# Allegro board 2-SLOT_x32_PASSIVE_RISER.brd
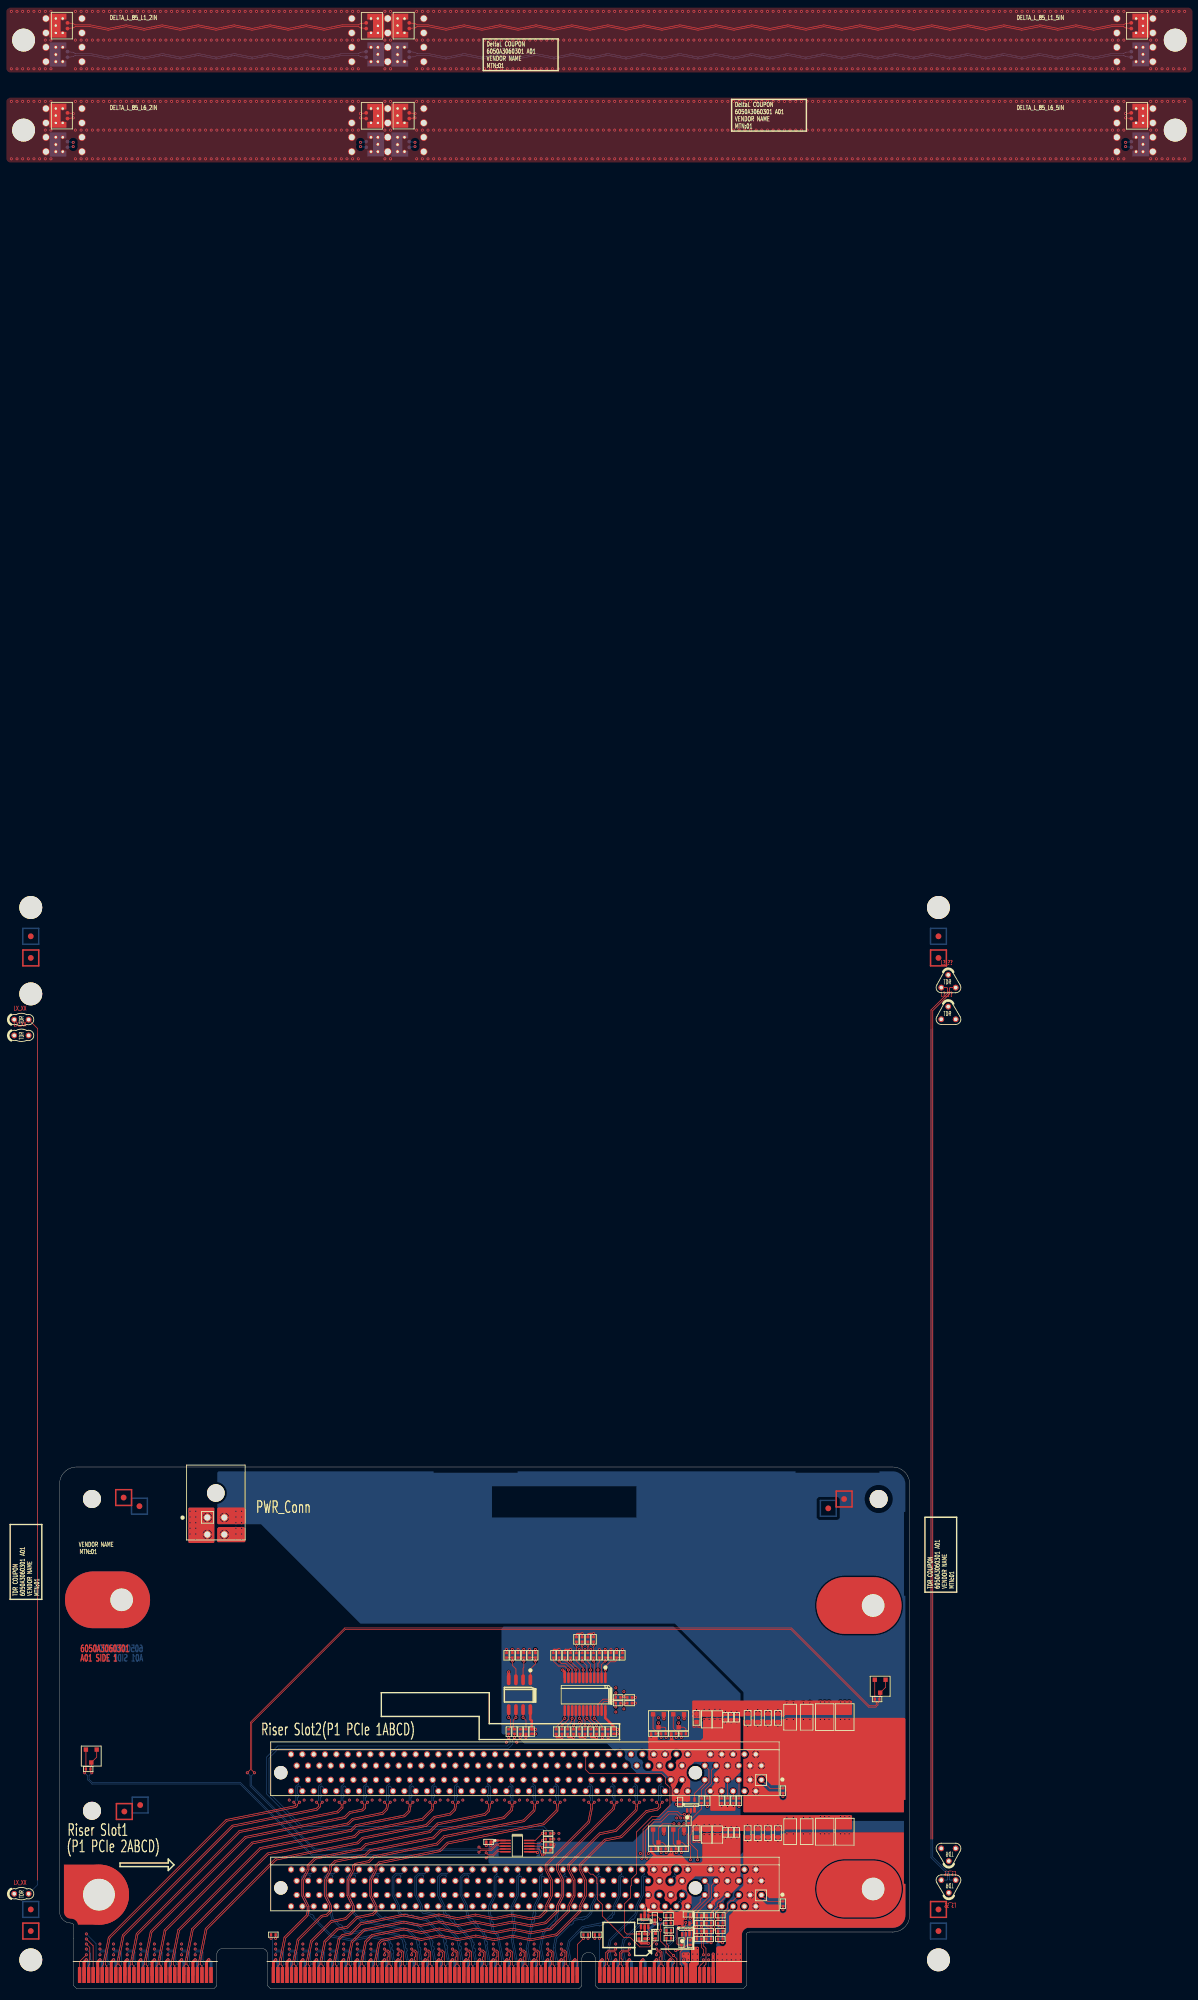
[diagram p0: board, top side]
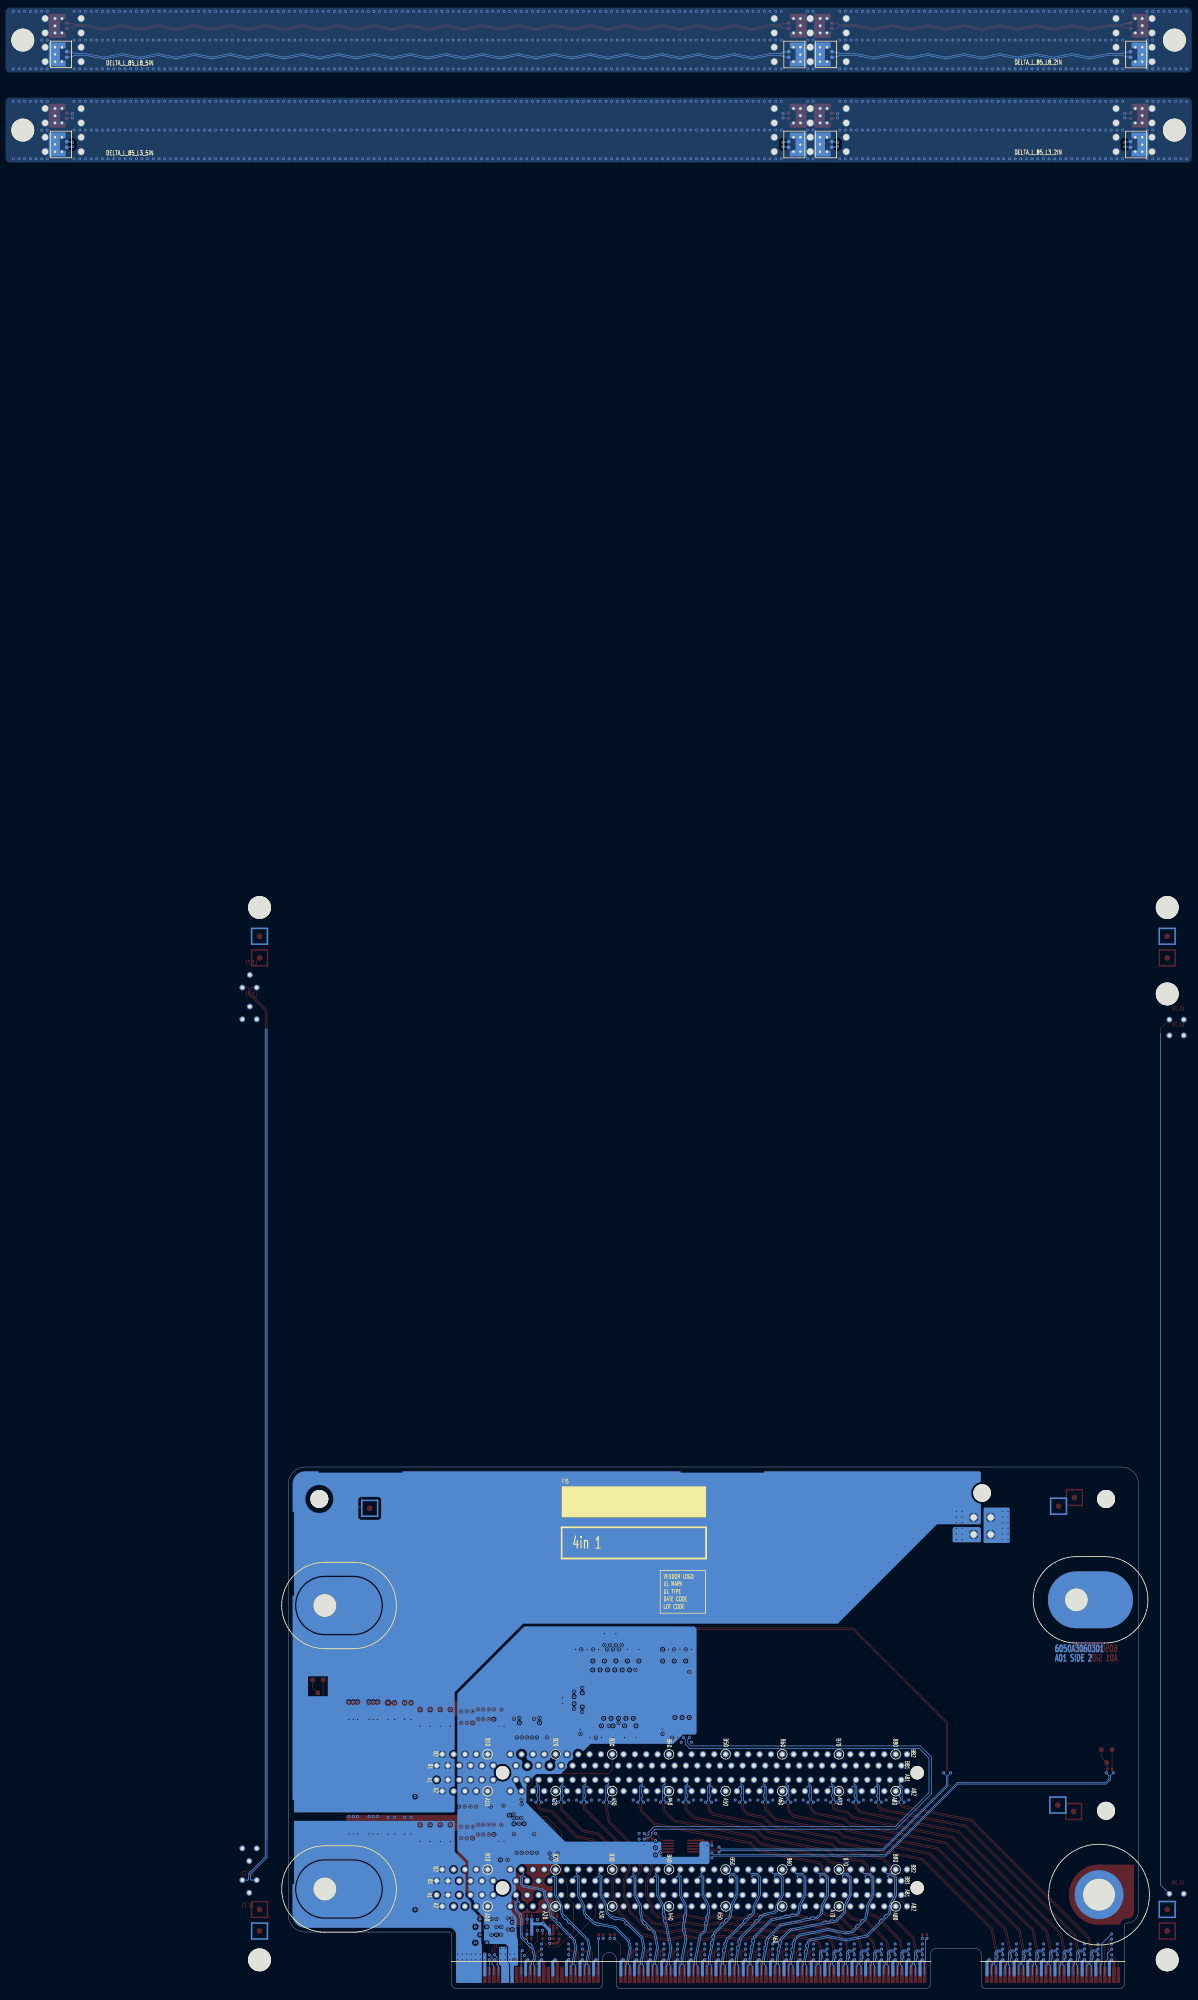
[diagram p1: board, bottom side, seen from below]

Outline 150 x 92 mm; copper layers: TOP, L2_GND, L3, L4_PWR, L5_PWR, L6, L7_GND, BOTTOM. Coordinates in mm from the lower left corner of the outline.
Outline path: 0,89 0,13.58 arc(0.59,12.16) 2,11.58 2,11.58 arc(2.36,11.43) 2.51,11.07 2.51,8.89 2.5,8.89 2.5,0.51 3.01,0 27.24,0 27.75,0.51 27.75,6.06 arc(28.05,6.78) 28.76,7.08 35.68,7.08 arc(36.4,6.78) 36.7,6.06 36.7,0.51 37.21,0 91.63,0 92.14,0.51 92.14,5.2 arc(93.34,6.4) 94.54,5.2 94.54,0.51 95.05,0 120.64,0 121.15,0.51 121.15,9.48 arc(121.3,9.84) 121.66,9.99 147,9.99 arc(149.12,10.86) 150,12.99 150,89 arc(149.12,91.12) 147,92 3,92 arc(0.88,91.12) 0,89

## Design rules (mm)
constraint set DEFAULT: min track width 0.102

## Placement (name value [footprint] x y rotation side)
C1  1uF  [A_MC-0603]  121.41 26.72 90 top
C2  1uF  [A_MC-0603]  123.19 26.72 90 top
C3  22uF  [A_MC-1206_A]  128.91 26.23 90 top
C4  22uF  [A_MC-1206_A]  131.83 26.23 90 top
C5  0.1UF  [A_MC-0402]  117.47 27.15 90 top
C6  0.1UF  [A_MC-0402]  118.49 27.15 90 top
C7  1uF  [A_MC-0402]  119.51 27.15 90 top
C8  4.7uF  [A_MC-0603]  124.97 26.72 90 top
C9  4.7uF  [A_MC-0603]  126.75 26.72 90 top
C10  4.7uF  [A_MC-0603]  112.39 26.72 90 top
C11  47uF  [A_MC-1210]  135 26.16 90 top
C12  10uF  [A_MC-0805]  116.08 26.3 90 top
C13  10uF  [A_MC-0805]  114.17 26.3 90 top
C14  0.1UF  [A_MC-0402]  103.24 9.64 270 top
C15  0.1UF  [A_MC-0402]  83.31 45.75 270 top
C16  0.1UF  [A_MC-0402]  97.79 45.75 270 top
C17  0.1UF  [A_MC-0402]  76.1 25.88 180 top
C18  22uF  [A_MC-1206_A]  128.91 46.42 90 top
C19  22uF  [A_MC-1206_A]  131.83 46.42 90 top
C20  47uF  [A_MC-1210]  135 46.35 90 top
C21  1uF  [A_MC-0603]  121.41 47.04 90 top
C22  1uF  [A_MC-0603]  126.75 47.04 90 top
C23  10uF  [A_MC-0805]  114.17 46.62 90 top
C24  10uF  [A_MC-0805]  116.08 46.62 90 top
C25  0.1UF  [A_MC-0402]  119.51 47.47 90 top
C26  0.1UF  [A_MC-0402]  117.47 47.47 90 top
C27  1uF  [A_MC-0402]  118.49 47.47 90 top
C28  4.7uF  [A_MC-0603]  124.97 47.04 90 top
C29  4.7uF  [A_MC-0603]  123.19 47.04 90 top
C30  100PF  [A_MC-0402]  144.65 51.05 180 top
C31  4.7uF  [A_MC-0603]  112.39 47.04 90 top
C32  100PF  [A_MC-0402]  4.65 38.73 0 top
C33  0.1UF  [A_MC-0402]  109.5 33.33 270 top
C34  0.1UF  [A_MC-0402]  110.46 13.08 0 top
C35  47uF  [A_MC-1210]  138.56 26.16 90 top
C36  47uF  [A_MC-1210]  138.56 46.35 90 top
J1  -  [A_FG-CN200-0P8MM_FULL_B]  120.13 2.4 180 top
J2  -  [FG-CN60-0P8MM_FULL_D]  26.72 2.4 180 top
J3  -  [A_CN164-2MM_FL]  123.84 16.52 180 top
J4  -  [A_CN164-2MM_FL]  123.84 36.84 180 top
J5  -  [A_SI_DELTAL_COUPON]  0.1 346.2 270 top
J6  -  [A_SI_DELTAL_COUPON]  55.41 346.2 90 top
J7  -  [A_SI_DELTAL_COUPON]  0.1 325.26 90 bottom
J8  -  [A_SI_DELTAL_COUPON]  55.41 325.25 270 bottom
J9  -  [A_SI_DELTAL_COUPON]  60.4 346.2 270 top
J10  -  [A_SI_DELTAL_COUPON]  190.4 346.2 90 top
J11  -  [A_SI_DELTAL_COUPON]  190.4 325.25 270 bottom
J12  -  [A_SI_DELTAL_COUPON]  60.4 325.26 90 bottom
J13  -  [A_CN4-3X3MM_ML_R_PIP]  26.07 83.1 180 top
J14  -  [A_SI_DELTAL_COUPON]  55.41 341.13 270 bottom
J15  -  [A_SI_DELTAL_COUPON]  55.41 330.33 90 top
J16  -  [A_SI_DELTAL_COUPON]  0.1 330.32 270 top
J17  -  [A_SI_DELTAL_COUPON]  0.1 341.13 90 bottom
J18  -  [A_SI_DELTAL_COUPON]  60.4 341.13 90 bottom
J19  -  [A_SI_DELTAL_COUPON]  190.4 330.33 90 top
J20  -  [A_SI_DELTAL_COUPON]  60.4 330.32 270 top
J22  -  [A_SI_DELTAL_COUPON]  190.4 341.13 270 bottom
MH1  -  [PAD_TP_D220_P339_K700_001]  6.95 16.58 270 bottom
MH2  -  [157X256_197_GRD_PTH]  10.95 68.58 180 bottom
MH3  -  [157X256_197_GRD_PTH]  143.55 17.58 180 bottom
MH4  -  [157X256_197_GRD_PTH]  143.55 67.58 180 bottom
NOREF  -  []  152 25.89 90 top
NOREF#2  -  []  12.74 101.75 0 top
NOREF#3  -  []  152 76.69 90 top
NOREF#4  -  [unnamed#2]  14.22 32.38 0 top
NOREF#5  -  [unnamed#2]  144.53 86.36 0 top
NOREF#6  -  []  73.41 91.59 0 top
NOREF#7  -  [unnamed#2]  196.85 327.79 270 top
NOREF#8  -  [unnamed#2]  -6.35 327.79 270 top
NOREF#9  -  []  -2.01 119.07 270 top
NOREF#10  -  []  12.74 91.59 0 top
NOREF#11  -  []  137.26 104.17 180 top
NOREF#12  -  [unnamed#2]  11.43 31.24 0 top
NOREF#13  -  [unnamed#2]  14.1 85.09 0 top
NOREF#14  -  [unnamed#2]  155.08 181.79 0 top
NOREF#15  -  []  137.26 91.59 0 top
NOREF#16  -  []  -2.01 76.69 270 top
NOREF#17  -  [unnamed#2]  11.3 86.61 0 top
NOREF#18  -  [unnamed#2]  -5.08 5.08 0 top
NOREF#19  -  [unnamed#2]  -5.08 185.6 0 top
NOREF#20  -  [unnamed#2]  155.08 185.6 0 top
NOREF#21  -  [unnamed#2]  -5.08 181.79 0 top
NOREF#22  -  [unnamed#2]  135.64 84.71 0 top
NOREF#23  -  [unnamed#2]  155.08 5.08 0 top
NOREF#24  -  [unnamed#2]  138.43 86.36 0 top
NOREF#25  -  [unnamed#2]  -6.35 343.67 270 top
NOREF#26  -  [unnamed#2]  155.08 10.16 180 top
NOREF#27  -  [unnamed#2]  196.85 343.67 270 top
NOREF#28  -  [unnamed#2]  5.71 31.37 0 top
NOREF#29  -  []  73.41 101.75 0 top
NOREF#30  -  [unnamed#2]  -5.08 190.68 0 top
NOREF#31  -  []  -2.01 25.89 270 top
NOREF#32  -  [unnamed#2]  -5.08 13.97 0 top
NOREF#33  -  [unnamed#2]  5.71 86.36 0 top
NOREF#34  -  [unnamed#2]  155.08 190.68 0 top
NOREF#35  -  [unnamed#2]  -5.08 10.16 0 top
NOREF#36  -  [unnamed#2]  -5.08 175.44 0 top
NOREF#37  -  [unnamed#2]  155.08 13.97 180 top
NOREF#38  -  []  -269.49 -130.56 0 top
NOREF#39  -  []  152 169.87 90 top
NOREF#40  -  []  152 119.07 90 top
NOREF#41  -  []  101.78 83.1 180 bottom
NOREF#42  -  []  101.78 75.86 180 bottom
NOREF#43  -  []  84.39 66.23 180 bottom
Q1  -  [A_SOT23FT]  106.63 48.39 180 top
Q2  -  [A_SOT23FT]  110.19 48.39 180 top
Q3  -  [A_SOT23FT]  110.19 28.07 180 top
Q4  -  [A_SOT23FT]  106.63 28.07 180 top
Q5  -  [A_SOT23FT]  145.75 54.48 180 top
Q6  -  [A_SOT23FT]  6.55 42.16 180 top
R1  0  [A_CR-0402]  111.25 7.72 90 top
R2  10K  [A_CR-0402]  96.77 45.75 270 top
R3  1K  [A_CR-0402]  95.76 44.93 90 top
R4  10K  [A_CR-0402]  78.87 58.39 90 top
R5  1K  [A_CR-0402]  79.88 59.21 270 top
R6  10K  [A_CR-0402]  97.28 58.39 90 top
R7  1K  [A_CR-0402]  96.27 59.21 270 top
R8  100  [A_CR-0402]  112.45 8.76 0 top
R9  10K  [A_CR-0402]  80.9 58.39 90 top
R10  1K  [A_CR-0402]  81.92 59.21 270 top
R11  10K  [A_CR-0402]  99.31 58.39 90 top
R12  1K  [A_CR-0402]  98.3 59.21 270 top
R13  10K  [A_CR-0402]  82.93 58.39 90 top
R14  100  [A_CR-0402]  112.45 10.16 0 top
R15  1K  [A_CR-0402]  83.95 59.21 270 top
R16  100  [A_CR-0402]  94.44 9.53 0 top
R17  10K  [A_CR-0402]  81.28 45.75 270 top
R18  100  [A_CR-0402]  93.24 9.53 180 top
R19  0  [A_CR-0402]  98.15 50.36 0 top
R20  0  [A_CR-0402]  107.09 8.89 0 top
R21  0  [A_CR-0402]  107.04 11.56 0 top
R22  4.7K  [A_CR-0402]  100.18 50.36 0 top
R23  4.7K  [A_CR-0402]  100.18 51.37 0 top
R24  4.7K  [A_CR-0402]  107.9 10.29 180 top
R25  4.7K  [A_CR-0402]  107.85 12.95 180 top
R26  0  [A_CR-0402]  109.73 7.72 90 top
R27  1K  [A_CR-0402]  82.3 44.93 90 top
R29  100  [A_CR-0402]  38.13 9.53 180 top
R30  0  [A_CR-0402]  80.26 45.75 270 top
R31  0  [A_CR-0402]  79.25 45.75 270 top
R32  0  [A_CR-0402]  94.23 58.39 90 top
R33  0  [A_CR-0402]  93.22 58.39 90 top
R34  0  [A_CR-0402]  92.2 58.39 90 top
R35  0  [A_CR-0402]  91.19 58.39 90 top
R36  0  [A_CR-0402]  85.79 27.39 0 top
R37  0  [A_CR-0402]  85.79 26.37 0 top
R38  100  [A_CR-0402]  127.64 34.52 90 top
R39  10K  [A_CR-0402]  117.86 33.55 270 top
R40  10K  [A_CR-0402]  118.87 33.55 270 top
R41  10K  [A_CR-0402]  114.3 32.74 90 top
R42  10K  [A_CR-0402]  116.84 33.55 270 top
R43  10K  [A_CR-0402]  119.89 32.74 90 top
R44  100  [A_CR-0402]  127.64 14.58 90 top
R45  10K  [A_CR-0402]  114.96 12.95 180 top
R46  10K  [A_CR-0402]  116.99 10.16 180 top
R47  10K  [A_CR-0402]  113.26 12.95 180 top
R48  10K  [A_CR-0402]  114.96 10.16 180 top
R49  10K  [A_CR-0402]  116.18 12.95 0 top
R50  0  [A_CR-0402]  114.96 11.56 180 top
R51  0  [A_CR-0402]  116.99 8.76 180 top
R52  0  [A_CR-0402]  111 29.18 90 top
R54  0  [A_CR-0402]  113.28 32.74 90 top
R55  0  [A_CR-0402]  114.96 8.76 180 top
R56  0  [A_CR-0402]  116.99 11.56 180 top
R57  0  [A_CR-0402]  98.15 51.37 0 top
R58  0  [A_CR-0402]  112.45 11.56 0 top
R59  0  [A_CR-0402]  106.96 44.96 180 top
R60  0  [A_CR-0402]  110.52 44.96 180 top
R61  0  [A_CR-0402]  110.52 24.64 180 top
R62  0  [A_CR-0402]  106.96 24.64 180 top
R63  4.7K  [A_CR-0402]  90.17 58.39 90 top
R64  4.7K  [A_CR-0402]  89.15 58.39 90 top
R65  4.7K  [A_CR-0402]  88.14 58.39 90 top
R66  4.7K  [A_CR-0402]  87.12 58.39 90 top
R67  4.7K  [A_CR-0402]  87.63 45.75 270 top
R68  4.7K  [A_CR-0402]  88.65 45.75 270 top
R69  4.7K  [A_CR-0402]  89.66 45.75 270 top
R70  4.7K  [A_CR-0402]  90.68 45.75 270 top
R71  4.7K  [A_CR-0402]  93.73 45.75 270 top
R72  4.7K  [A_CR-0402]  94.74 45.75 270 top
R74  100K  [A_CR-0402]  105.03 12.17 90 top
R98  4.7K  [A_CR-0402]  102.23 9.64 270 top
R99  4.7K  [A_CR-0402]  105.16 8.86 90 top
R100  4.7K  [A_CR-0402]  108.74 24.64 180 top
R101  4.7K  [A_CR-0402]  105.18 24.64 180 top
R102  4.7K  [A_CR-0402]  105.18 44.96 180 top
R103  4.7K  [A_CR-0402]  108.74 44.96 180 top
R104  4.7K  [A_CR-0402]  85.79 24.38 0 top
R105  4.7K  [A_CR-0402]  85.83 25.4 0 top
R106  4.7K  [A_CR-0402]  91.19 61.19 90 top
R107  4.7K  [A_CR-0402]  92.2 61.19 90 top
R108  4.7K  [A_CR-0402]  93.22 61.19 90 top
R109  4.7K  [A_CR-0402]  94.23 61.19 90 top
R110  4.7K  [A_CR-0402]  91.69 45.75 270 top
R111  4.7K  [A_CR-0402]  92.71 45.75 270 top
R112  4.7K  [A_CR-0402]  95.25 58.39 90 top
TDR1  -  [A_COUPON1X3]  155.57 176.56 0 top
TDR2  -  [A_COUPON1X3]  155.57 170.97 0 top
TDR3  -  [A_COUPON1X3]  158.12 24.74 180 top
TDR4  -  [A_COUPON1X3]  158.12 19.15 180 top
TDR5  -  [A_COUPON1X2]  -8 170.91 0 top
TDR6  -  [A_COUPON1X2]  -8 168.12 0 top
TDR8  -  [A_COUPON1X2]  -8 16.73 0 top
U1  -  [A_SC70-0P65MM-6P]  103.89 12.83 180 top
U2  -  [A_SSOP24-25P6X228]  96.29 54.84 180 top
U4  -  [A_MSOP10-19P7X165]  78.68 26.14 270 top
U5  -  [A_SOIC8-50X208]  83.06 54.48 180 top
U6  -  [A_SC70-0P65MMX1P9MM]  109.84 9.59 0 top
U7  -  [A_SC70-0P65MMX1P9MM]  110.73 31.43 0 top

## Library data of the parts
C1 C2 C21 C22 = A_CAP: alternate symbols: (); part number: A_CAP_0603-1UF,16V,+/-10%,X7R,6010B0106601; signal model: C2_6010B0106601_1U; tolerance: +/-10%
C3 C4 C18 C19 = A_CAP: alternate symbols: (); part number: A_CAP_1206-22UF,16V,+/-10%,X6S,6010B0309401; signal model: C2_6010B0309401_22U; tolerance: +/-10%
C5 C6 C14-C17 C25 C26 C33 C34 = A_CAP: alternate symbols: (A_MC-0402_CUTPAD,A_MC-0402_CUTPAD_0P8MM); part number: A_CAP_0402-0.1UF,16V,+/-10%,X7R,6010A0036403; signal model: C2_6010A0036403_0_1U; tolerance: +/-10%
C7 C27 = A_CAP: alternate symbols: (A_MC-0402_CUTPAD,A_MC-0402_CUTPAD_0P8MM); part number: A_CAP_0402-1UF,6.3V,+/-10%,X7R,6010B0435701; signal model: C2_6010B0435701_1U; tolerance: +/-10%
C8-C10 C28 C29 C31 = A_CAP: alternate symbols: (); part number: A_CAP_0603-4.7UF,16V,+/-10%,X6S,6010B0347201; signal model: C2_6010B0347201_4_7U; tolerance: +/-10%
C11 C20 C35 C36 = A_CAP: alternate symbols: (); part number: A_CAP_1210-47UF,16V,+/-20%,X6S,6010B0367101; signal model: C2_6010B0367101_47U; tolerance: +/-20%
C12 C13 C23 C24 = A_CAP: alternate symbols: (); part number: A_CAP_0805-10UF,16V,+/-10%,X7R,6010B0152001; signal model: C2_6010B0152001_10U; tolerance: +/-10%
C30 C32 = A_CAP: alternate symbols: (A_MC-0402_CUTPAD,A_MC-0402_CUTPAD_0P8MM); part number: A_CAP_0402-100PF,50V,+/-5%,NP0,6010A003610J; signal model: C2_6010A003610J_100P; tolerance: +/-5%
J1 = A_HSEC8_2X100_FG: part number: A_HSEC8_2X100_FG_HSEC8_FG-FG-CN200-0P8MM_FULL_B
J2 = A_2X30_2MP_B_FG: alternate symbols: (); part number: A_2X30_2MP_B_FG_FG-FG-CN60-0P8MM_FULL_D
J3 J4 = A_PCIE16X: alternate symbols: (); part number: A_PCIE16X_PCIE16X-6012B0820801
J5-J12 J14-J20 J22 = A_SI_DELTAL_COUPON: part number: A_SI_DELTAL_COUPON_COUPON-SI_DELTAL_COUPON
J13 = A_2X2: alternate symbols: (); part number: A_2X2_CN4-6012B0884101
MH1 = A_TOOL1X1: part number: A_TOOL1X1_1X1-PAD_TP_D220_P339_K700_001
MH2-MH4 = A_TOOL1X1: part number: A_TOOL1X1_1X1-157X256_197_GRD_PTH
Q1-Q4 = A_NMFET_A: alternate symbols: (); part number: A_NMFET_A_SOT23-NX7002BKR,-,60V,+/-20V,6015B0042607
Q5 Q6 = A_NPN: alternate symbols: (); part number: A_NPN_SM-PMBT3904,40V,-,-,6015B0007101
R1 R19-R21 R26 R30-R37 R50-R52 R54-R62 = A_RES_SMT: alternate symbols: (A_CR-0402_CUTPAD_0P8MM,A_CR-0402_CUTPAD); part number: A_RES_SMT_0402-0,5%,1A,6013B0051101; signal model: R2_6013B0051101_0; tolerance: 5%
R2 R4 R6 R9 R11 R13 R17 R39-R43 R45-R49 = A_RES_SMT: alternate symbols: (A_CR-0402_CUTPAD_0P8MM,A_CR-0402_CUTPAD); part number: A_RES_SMT_0402-10K,1%,1/16,6013A008830M; signal model: R2_6013A008830M_10K; tolerance: 1%
R3 R5 R7 R10 R12 R15 R27 = A_RES_SMT: alternate symbols: (A_CR-0402_CUTPAD_0P8MM,A_CR-0402_CUTPAD); part number: A_RES_SMT_0402-1K,1%,1/16W,6013A0088009; signal model: R2_6013A0088009_1K; tolerance: 1%
R8 R14 R16 R18 R29 R38 R44 = A_RES_SMT: alternate symbols: (A_CR-0402_CUTPAD_0P8MM,A_CR-0402_CUTPAD); part number: A_RES_SMT_0402-100,1%,1/16W,6013A008760S; signal model: R2_6013A008760S_100; tolerance: 1%
R22-R25 R63-R72 R98-R112 = A_RES_SMT: alternate symbols: (A_CR-0402_CUTPAD_0P8MM,A_CR-0402_CUTPAD); part number: A_RES_SMT_0402-4.7K,1%,1/16W,6013B0080101; signal model: R2_6013B0080101_4_7K; tolerance: 1%
R74 = A_RES_SMT: alternate symbols: (A_CR-0402_CUTPAD_0P8MM,A_CR-0402_CUTPAD); part number: A_RES_SMT_0402-100K,1%,1/16,6013A0088705; signal model: R2_6013A0088705_100K; tolerance: 1%
TDR1-TDR4 = A_COUPON1X3: part number: A_COUPON1X3_1X3-COUPON1X3-00
TDR5 TDR6 TDR8 = A_COUPON1X2: part number: A_COUPON1X2_1X2-COUPON1X2-00
U1 = A_NC7WV07: alternate symbols: (); part number: A_NC7WV07_SC70-NC7WV07P6X,6019B0664001
U2 = A_PCA9548A: alternate symbols: (); part number: A_PCA9548A_TSSOP-PCA9548APW,118,6019B0191601
U4 = A_EMC1413: alternate symbols: (); part number: A_EMC1413_MSOP-EMC1413-A-AIZL-TR,6019B1799701
U5 = A_24CX: alternate symbols: (); part number: A_24CX_SOIC8-24C64CN-SH-T,6019B0493601
U6 U7 = A_TSG17: alternate symbols: (); part number: A_TSG17_SC70-SN74LVC1G17DCKR,6019B0306901

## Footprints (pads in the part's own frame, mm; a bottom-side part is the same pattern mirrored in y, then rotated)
157X256_197_GRD_PTH
  oval 15.011x10.008 hole 3.988: 1(0,0)
A_CN4-3X3MM_ML_R_PIP
  round 3.099 hole 3.099 unplated: (-1.5,-4.32)
  round 1.448 hole 1.067: 1(0,0) 2(-3,0) 3(0,3) 4(-3,3)
A_CN164-2MM_FL
  round 2.362 hole 2.362 unplated: (11.65,-1.25) (84.8,-1.25)
  round 1.092 hole 0.711: A1(0,0) A2(0.999,2) A3(2,0) A4(3,2) A5(4,0) A6(5,2) A7(5.999,0) A8(7,2) A9(8,0) A10(9,2) A11(10,0) A12(13,2) A13(14,0) A14(15,2) A15(15.999,0) A16(17,2) A17(18,0) A18(19,2) A19(20,0) A20(20.999,2) A21(22,0) A22(23,2) A23(24,0) A24(25,2) A25(25.999,0) A26(27,2) A27(28,0) A28(29,2) A29(30,0) A30(30.999,2) A31(32,0) A32(33,2) A33(34,0) A34(35,2) A35(35.999,0) A36(37,2) A37(38,0) A38(39,2) A39(40,0) A40(40.999,2) A41(42,0) A42(43,2) A43(44,0) A44(45,2) A45(45.999,0) A46(47,2) A47(48,0) A48(49,2) A49(50,0) A50(50.999,2) A51(52,0) A52(53,2) A53(54,0) A54(55,2) A55(55.999,0) A56(57,2) A57(58,0) A58(59,2) A59(60,0) A60(60.999,2) A61(62,0) A62(63,2) A63(64,0) A64(65,2) A65(66.001,0) A66(67,2) A67(68,0) A68(69,2) A69(70,0) A70(71.001,2) A71(72,0) A72(73,2) A73(74,0) A74(75,2) A75(76.001,0) A76(77,2) A77(78,0) A78(79,2) A79(80,0) A80(81.001,2) A81(82,0) A82(83,2) B1(0,-2.501) B2(0.999,-4.5) B3(2,-2.501) B4(3,-4.5) B5(4,-2.501) B6(5,-4.5) B7(5.999,-2.501) B8(7,-4.5) B9(8,-2.501) B10(9,-4.5) B11(10,-2.501) B12(13,-4.5) B13(14,-2.501) B14(15,-4.5) B15(15.999,-2.501) B16(17,-4.5) B17(18,-2.501) B18(19,-4.5) B19(20,-2.501) B20(20.999,-4.5) B21(22,-2.501) B22(23,-4.5) B23(24,-2.501) B24(25,-4.5) B25(25.999,-2.501) B26(27,-4.5) B27(28,-2.501) B28(29,-4.5) B29(30,-2.501) B30(30.999,-4.5) B31(32,-2.501) B32(33,-4.5) B33(34,-2.501) B34(35,-4.5) B35(35.999,-2.501) B36(37,-4.5) B37(38,-2.501) B38(39,-4.5) B39(40,-2.501) B40(40.999,-4.5) B41(42,-2.501) B42(43,-4.5) B43(44,-2.501) B44(45,-4.5) B45(45.999,-2.501) B46(47,-4.5) B47(48,-2.501) B48(49,-4.5) B49(50,-2.501) B50(50.999,-4.5) B51(52,-2.501) B52(53,-4.5) B53(54,-2.501) B54(55,-4.5) B55(55.999,-2.501) B56(57,-4.5) B57(58,-2.501) B58(59,-4.5) B59(60,-2.501) B60(60.999,-4.5) B61(62,-2.501) B62(63,-4.5) B63(64,-2.501) B64(65,-4.5) B65(66.001,-2.501) B66(67,-4.5) B67(68,-2.501) B68(69,-4.5) B69(70,-2.501) B70(71.001,-4.5) B71(72,-2.501) B72(73,-4.5) B73(74,-2.501) B74(75,-4.5) B75(76.001,-2.501) B76(77,-4.5) B77(78,-2.501) B78(79,-4.5) B79(80,-2.501) B80(81.001,-4.5) B81(82,-2.501) B82(83,-4.5)
A_COUPON1X2
  round 1.016 hole 0.61: 1(0,0) 2(2.54,0)
A_COUPON1X3
  round 1.016 hole 0.61: 1(1.219,2.235) 2(0,0) 3(2.54,0)
A_CR-0402
  rect 0.406x0.508 smd: 1(0,0) 2(0.813,0)
A_FG-CN200-0P8MM_FULL_B
  rect 0.559x2.794 smd: 1(0,0) 2(0,0) 3(0.8,0) 4(0.8,0) 5(1.6,0) 6(1.6,0) 7(2.4,0) 8(2.4,0) 9(3.2,0) 10(3.2,0) 11(4,0) 12(4,0) 13(4.8,0) 14(4.8,0) 15(5.6,0) 16(5.6,0) 17(6.4,0) 18(6.4,0) 19(7.2,0) 20(7.2,0) 21(8,0) 22(8,0) 23(8.8,0) 24(8.8,0) 25(9.6,0) 26(9.6,0) 27(10.4,0) 28(10.4,0) 29(11.2,0) 30(11.2,0) 31(12,0) 32(12,0) 33(12.8,0) 34(12.8,0) 35(13.6,0) 36(13.6,0) 37(14.4,0) 38(14.4,0) 39(15.2,0) 40(15.2,0) 41(16,0) 42(16,0) 43(16.8,0) 44(16.8,0) 45(17.6,0) 46(17.6,0) 47(18.4,0) 48(18.4,0) 49(19.2,0) 50(19.2,0) 51(20,0) 52(20,0) 53(20.8,0) 54(20.8,0) 55(21.6,0) 56(21.6,0) 57(22.4,0) 58(22.4,0) 59(23.2,0) 60(23.2,0) 61(24,0) 62(24,0) 63(24.8,0) 64(24.8,0) 65(28.8,0) 66(28.8,0) 67(29.6,0) 68(29.6,0) 69(30.4,0) 70(30.4,0) 71(31.2,0) 72(31.2,0) 73(32,0) 74(32,0) 75(32.8,0) 76(32.8,0) 77(33.6,0) 78(33.6,0) 79(34.4,0) 80(34.4,0) 81(35.2,0) 82(35.2,0) 83(36,0) 84(36,0) 85(36.8,0) 86(36.8,0) 87(37.6,0) 88(37.6,0) 89(38.4,0) 90(38.4,0) 91(39.2,0) 92(39.2,0) 93(40,0) 94(40,0) 95(40.8,0) 96(40.8,0) 97(41.6,0) 98(41.6,0) 99(42.4,0) 100(42.4,0) 101(43.2,0) 102(43.2,0) 103(44,0) 104(44,0) 105(44.8,0) 106(44.8,0) 107(45.6,0) 108(45.6,0) 109(46.4,0) 110(46.4,0) 111(47.2,0) 112(47.2,0) 113(48,0) 114(48,0) 115(48.8,0) 116(48.8,0) 117(49.6,0) 118(49.6,0) 119(50.4,0) 120(50.4,0) 121(51.2,0) 122(51.2,0) 123(52,0) 124(52,0) 125(52.8,0) 126(52.8,0) 127(53.6,0) 128(53.6,0) 129(54.4,0) 130(54.4,0) 131(55.2,0) 132(55.2,0) 133(56,0) 134(56,0) 135(56.8,0) 136(56.8,0) 137(57.6,0) 138(57.6,0) 139(58.4,0) 140(58.4,0) 141(59.2,0) 142(59.2,0) 143(60,0) 144(60,0) 145(60.8,0) 146(60.8,0) 147(61.6,0) 148(61.6,0) 149(62.4,0) 150(62.4,0) 151(63.2,0) 152(63.2,0) 153(64,0) 154(64,0) 155(64.8,0) 156(64.8,0) 157(65.6,0) 158(65.6,0) 159(66.4,0) 160(66.4,0) 161(67.2,0) 162(67.2,0) 163(68,0) 164(68,0) 165(68.8,0) 166(68.8,0) 167(69.6,0) 168(69.6,0) 169(70.4,0) 170(70.4,0) 171(71.2,0) 172(71.2,0) 173(72,0) 174(72,0) 175(72.8,0) 176(72.8,0) 177(73.6,0) 178(73.6,0) 179(74.4,0) 180(74.4,0) 181(75.2,0) 182(75.2,0) 183(76,0) 184(76,0) 185(76.8,0) 186(76.8,0) 187(77.6,0) 188(77.6,0) 189(78.4,0) 190(78.4,0) 191(79.2,0) 192(79.2,0) 193(80,0) 194(80,0) 195(80.8,0) 196(80.8,0) 197(81.6,0) 198(81.6,0) 199(82.4,0) 200(82.4,0)
A_MC-0402
  rect 0.406x0.508 smd: 1(0,0) 2(0.813,0)
A_MC-0603
  rect 0.711x0.762 smd: 1(0,0) 2(1.422,0)
A_MC-0805
  rect 0.813x1.219 smd: 1(0,0) 2(1.753,0)
A_MC-1206_A
  rect 1.168x1.778 smd: 1(0,0) 2(2.921,0)
A_MC-1210
  custom 0.305x0.305 smd: 1(0,0) 2(3.048,0)
A_MSOP10-19P7X165
  custom 0.064x0.064 smd: 1(0,0) 2(0.5,0) 3(1.001,0) 4(1.501,0) 5(2.002,0) 6(2.002,4.191) 7(1.501,4.191) 8(1.001,4.191) 9(0.5,4.191) 10(0,4.191)
A_SC70-0P65MM-6P
  rect 0.406x0.813 smd: 1(0,0) 2(0.65,0) 3(1.3,0) 4(1.3,1.9) 5(0.65,1.9) 6(0,1.9)
A_SC70-0P65MMX1P9MM
  rect 0.406x0.762 smd: 1(0,0) 2(0.65,0) 3(1.3,0) 4(1.3,1.9) 5(0,1.9)
A_SI_DELTAL_COUPON
  round 0.66 smd: 1(-0.504,1.301) 2(0.497,1.301)
  custom 0.743x0.743 smd: GND1(-0.009,-0.37)
  round 0.66 hole 0.406: GND2(-1.27,0.457) GND3(-1.27,-0.762) GND4(-0.025,-0.762) GND5(1.27,-0.762) GND6(1.27,0.457)
  round 1.295 hole 1.041: MP1(-1.274,3.852) MP2(1.266,3.852) MP3(-1.274,-2.498) MP4(1.266,-2.498)
A_SOIC8-50X208
  oval 0.635x1.93 smd: 1(0,0) 2(1.27,0) 3(2.54,0) 4(3.81,0) 5(3.81,5.283) 6(2.54,5.283) 7(1.27,5.283) 8(0,5.283)
A_SOT23FT
  rect 0.762x0.762 smd: 1(0,0) 2(1.905,0) 3(0.953,2.286)
A_SSOP24-25P6X228
  oval 0.457x1.93 smd: 1(0,0) 2(0.65,0) 3(1.3,0) 4(1.951,0) 5(2.601,0) 6(3.251,0) 7(3.901,0) 8(4.552,0) 9(5.202,0) 10(5.852,0) 11(6.502,0) 12(7.153,0) 13(7.153,5.791) 14(6.502,5.791) 15(5.852,5.791) 16(5.202,5.791) 17(4.552,5.791) 18(3.901,5.791) 19(3.251,5.791) 20(2.601,5.791) 21(1.951,5.791) 22(1.3,5.791) 23(0.65,5.791) 24(0,5.791)
FG-CN60-0P8MM_FULL_D
  rect 0.559x2.794 smd: 1(0,0) 2(0,0) 3(0.8,0) 4(0.8,0) 5(1.6,0) 6(1.6,0) 7(2.4,0) 8(2.4,0) 9(3.2,0) 10(3.2,0) 11(4,0) 12(4,0) 13(4.8,0) 14(4.8,0) 15(5.6,0) 16(5.6,0) 17(6.4,0) 18(6.4,0) 19(7.2,0) 20(7.2,0) 21(8,0) 22(8,0) 23(8.8,0) 24(8.8,0) 25(9.6,0) 26(9.6,0) 27(10.4,0) 28(10.4,0) 29(11.2,0) 30(11.2,0) 31(12,0) 32(12,0) 33(12.8,0) 34(12.8,0) 35(13.6,0) 36(13.6,0) 37(14.4,0) 38(14.4,0) 39(15.2,0) 40(15.2,0) 41(16,0) 42(16,0) 43(16.8,0) 44(16.8,0) 45(17.6,0) 46(17.6,0) 47(18.4,0) 48(18.4,0) 49(19.2,0) 50(19.2,0) 51(20,0) 52(20,0) 53(20.8,0) 54(20.8,0) 55(21.6,0) 56(21.6,0) 57(22.4,0) 58(22.4,0) 59(23.2,0) 60(23.2,0)
PAD_TP_D220_P339_K700_001
  round 10.592 hole 5.588: 1(0,0)
unnamed#2
  round 1.016 smd: (0,0)

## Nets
GND: C1.2(B) C2.2(B) C3.2(B) C4.2(B) C5.2(B) C6.2(B) C7.2(B) C8.2(B) C9.2(B) C10.2(B) C11.2(B) C12.2(B) C13.2(B) C14.2(B) C15.2(B) C16.2(B) C17.2(B) C18.2(B) C19.2(B) C20.2(B) C21.2(B) C22.2(B) C23.2(B) C24.2(B) C25.2(B) C26.2(B) C27.2(B) C28.2(B) C29.2(B) C31.2(B) C33.2(B) C34.2(B) C35.2(B) C36.2(B) J1.13 J1.14 J1.26 J1.31 J1.34 J1.37 J1.40 J1.43 J1.46 J1.49 J1.52 J1.55 J1.58 J1.61 J1.64 J1.65 J1.68 J1.71 J1.74 J1.77 J1.80 J1.83 J1.86 J1.89 J1.92 J1.95 J1.98 J1.101 J1.104 J1.107 J1.110 J1.113 J1.116 J1.119 J1.122 J1.125 J1.128 J1.131 J1.134 J1.137 J1.140 J1.143 J1.146 J1.149 J1.152 J1.155 J1.158 J1.161 J1.164 J1.167 J1.170 J1.173 J1.176 J1.179 J1.182 J1.185 J1.188 J1.191 J1.194 J1.197 J1.200 J2.1 J2.4 J2.7 J2.10 J2.13 J2.16 J2.19 J2.22 J2.25 J2.28 J2.31 J2.34 J2.37 J2.40 J2.43 J2.46 J2.49 J2.52 J2.55 J2.58 J3.A4 J3.A12 J3.A15 J3.A18 J3.A20 J3.A23 J3.A24 J3.A27 J3.A28 J3.A31 J3.A34 J3.A37 J3.A38 J3.A41 J3.A42 J3.A45 J3.A46 J3.A49 J3.A51 J3.A54 J3.A55 J3.A58 J3.A59 J3.A62 J3.A63 J3.A66 J3.A67 J3.A70 J3.A71 J3.A74 J3.A75 J3.A78 J3.A79 J3.A82 J3.B4 J3.B7 J3.B13 J3.B16 J3.B18 J3.B21 J3.B22 J3.B25 J3.B26 J3.B29 J3.B32 J3.B35 J3.B36 J3.B39 J3.B40 J3.B43 J3.B44 J3.B47 J3.B49 J3.B52 J3.B53 J3.B56 J3.B57 J3.B60 J3.B61 J3.B64 J3.B65 J3.B68 J3.B69 J3.B72 J3.B73 J3.B76 J3.B77 J3.B80 J4.A4 J4.A12 J4.A15 J4.A18 J4.A20 J4.A23 J4.A24 J4.A27 J4.A28 J4.A31 J4.A34 J4.A37 J4.A38 J4.A41 J4.A42 J4.A45 J4.A46 J4.A49 J4.A51 J4.A54 J4.A55 J4.A58 J4.A59 J4.A62 J4.A63 J4.A66 J4.A67 J4.A70 J4.A71 J4.A74 J4.A75 J4.A78 J4.A79 J4.A82 J4.B4 J4.B7 J4.B13 J4.B16 J4.B18 J4.B21 J4.B22 J4.B25 J4.B26 J4.B29 J4.B32 J4.B35 J4.B36 J4.B39 J4.B40 J4.B43 J4.B44 J4.B47 J4.B49 J4.B52 J4.B53 J4.B56 J4.B57 J4.B60 J4.B61 J4.B64 J4.B65 J4.B68 J4.B69 J4.B72 J4.B73 J4.B76 J4.B77 J4.B80 J13.1 J13.3 MH1.1 MH2.1 MH3.1 MH4.1 R3.1 R5.1 R7.1 R8.1 R10.1 R12.1 R14.1 R15.1 R16.1 R18.1 R27.1 R29.1 R38.1 R41.1 R43.1 R44.1 R47.1 R49.1 U1.2 U2.12(VSS) U4.6 U5.4 U6.3 U7.3
GND_A: TDR1.1 TDR2.1 TDR3.1 TDR4.1 TDR5.1 TDR6.1 TDR8.1
GND_D: J5.GND1 J5.GND2 J5.GND3 J5.GND4 J5.GND5 J5.GND6 J5.MP1 J5.MP2 J5.MP3 J5.MP4 J6.GND1 J6.GND2 J6.GND3 J6.GND4 J6.GND5 J6.GND6 J6.MP1 J6.MP2 J6.MP3 J6.MP4 J9.GND1 J9.GND2 J9.GND3 J9.GND4 J9.GND5 J9.GND6 J9.MP1 J9.MP2 J9.MP3 J9.MP4 J10.GND1 J10.GND2 J10.GND3 J10.GND4 J10.GND5 J10.GND6 J10.MP1 J10.MP2 J10.MP3 J10.MP4 J14.GND1 J14.GND2 J14.GND3 J14.GND4 J14.GND5 J14.GND6 J14.MP1 J14.MP2 J14.MP3 J14.MP4 J17.GND1 J17.GND2 J17.GND3 J17.GND4 J17.GND5 J17.GND6 J17.MP1 J17.MP2 J17.MP3 J17.MP4 J18.GND1 J18.GND2 J18.GND3 J18.GND4 J18.GND5 J18.GND6 J18.MP1 J18.MP2 J18.MP3 J18.MP4 J22.GND1 J22.GND2 J22.GND3 J22.GND4 J22.GND5 J22.GND6 J22.MP1 J22.MP2 J22.MP3 J22.MP4
GND_K: J7.GND1 J7.GND2 J7.GND3 J7.GND4 J7.GND5 J7.GND6 J7.MP1 J7.MP2 J7.MP3 J7.MP4 J8.GND1 J8.GND2 J8.GND3 J8.GND4 J8.GND5 J8.GND6 J8.MP1 J8.MP2 J8.MP3 J8.MP4 J11.GND1 J11.GND2 J11.GND3 J11.GND4 J11.GND5 J11.GND6 J11.MP1 J11.MP2 J11.MP3 J11.MP4 J12.GND1 J12.GND2 J12.GND3 J12.GND4 J12.GND5 J12.GND6 J12.MP1 J12.MP2 J12.MP3 J12.MP4 J15.GND1 J15.GND2 J15.GND3 J15.GND4 J15.GND5 J15.GND6 J15.MP1 J15.MP2 J15.MP3 J15.MP4 J16.GND1 J16.GND2 J16.GND3 J16.GND4 J16.GND5 J16.GND6 J16.MP1 J16.MP2 J16.MP3 J16.MP4 J19.GND1 J19.GND2 J19.GND3 J19.GND4 J19.GND5 J19.GND6 J19.MP1 J19.MP2 J19.MP3 J19.MP4 J20.GND1 J20.GND2 J20.GND3 J20.GND4 J20.GND5 J20.GND6 J20.MP1 J20.MP2 J20.MP3 J20.MP4
P3V3: C5.1 C6.1 C7.1 C12.1 C13.1 C34.1 J1.21 J1.22 J1.23 J1.24 J3.A9 J3.A10 J3.B8 Q3.1 Q4.1 R45.2(B) R46.2(B) R48.2(B) R99.2(B) R100.2(B) R101.2(B) U6.5
P3V3_B: C23.1 C24.1 C25.1 C26.1 C27.1 C33.1 J4.A9 J4.A10 J4.B8 J13.4 Q1.1 Q2.1 R39.2(B) R40.2(B) R42.2(B) R98.2(B) R102.2(B) R103.2(B) U7.5
P3V3_STBY: C10.1 C14.1 C15.1 C16.1 C17.1 C31.1 J1.25 J3.B10 J4.B10 R2.2(B) R4.2(B) R6.2(B) R9.2(B) R11.2(B) R13.2(B) R17.2(B) R22.2(B) R23.2(B) R24.2(B) R25.2(B) R63.2(B) R64.2(B) R65.2(B) R66.2(B) R67.2(B) R68.2(B) R69.2(B) R70.2(B) R71.2(B) R72.2(B) R74.1 R104.2(B) R105.2(B) R106.2(B) R107.2(B) R108.2(B) R109.2(B) R110.2(B) R111.2(B) R112.2(B) U1.5 U2.24 U4.1(VDD) U5.8
P12V: C1.1 C2.1 C3.1 C4.1 C8.1 C9.1 C11.1 C35.1 J1.1 J1.2 J1.3 J1.4 J1.5 J1.6 J1.7 J1.8 J1.9 J1.10 J1.11 J1.12 J3.A2 J3.A3 J3.B1 J3.B2 J3.B3
P12V_B: C18.1 C19.1 C20.1 C21.1 C22.1 C28.1 C29.1 C36.1 J4.A2 J4.A3 J4.B1 J4.B2 J4.B3 J13.2
ALERT_N: R105.1 U4.8
CLK_100M_BUF_SLOT4A_DN: J1.35 J3.A14
CLK_100M_BUF_SLOT4A_DP: J1.33 J3.A13
CLK_100M_BUF_SLOT4B_DN: J1.38 J4.A14
CLK_100M_BUF_SLOT4B_DP: J1.36 J4.A13
DC_CLK_100M_BUF_SLOT4C_DN: J1.41
DC_CLK_100M_BUF_SLOT4C_DP: J1.39
DC_CLK_100M_BUF_SLOT4D_DN: J1.44
DC_CLK_100M_BUF_SLOT4D_DP: J1.42
DC_CLK_100M_BUF_SLOT4E_DN: J1.47
DC_CLK_100M_BUF_SLOT4E_DP: J1.45
DC_CLK_100M_BUF_SLOT4F_DN: J1.50
DC_CLK_100M_BUF_SLOT4F_DP: J1.48
DC_FM_J3_CFG0: J3.B17
DC_FM_J3_CFG1: J3.B31
DC_FM_J3_CFG2: J3.B48
DC_FM_J3_CFG3: J3.B81
DC_FM_J4_CFG0: J4.B17
DC_FM_J4_CFG1: J4.B31
DC_FM_J4_CFG2: J4.B48
DC_FM_J4_CFG3: J4.B81
DC_IRQ_OOB_MGMT_RISER_ALERT_N: J1.16
DC_J3_A19: J3.A19
DC_J3_A32: J3.A32
DC_J3_A33: J3.A33
DC_J3_A50: J3.A50
DC_J3_B12: J3.B12
DC_J3_B82: J3.B82
DC_J4_A19: J4.A19
DC_J4_A32: J4.A32
DC_J4_A33: J4.A33
DC_J4_A50: J4.A50
DC_J4_B12: J4.B12
DC_J4_B82: J4.B82
DC_J134_2: J2.2
DC_SMB_ALT_CPU_N: J1.27
DC_U6_NC: U6.1
DC_U7_NC: U7.1
DC_USB2_CPU1_SLOT4_DN: J2.57
DC_USB2_CPU1_SLOT4_DP: J2.59
DELTA_L_85_OHMS_L1_2IN_DN: J5.1 J6.2(S2)
DELTA_L_85_OHMS_L1_2IN_DP: J5.2(S2) J6.1
DELTA_L_85_OHMS_L1_5IN_DN: J9.1 J10.2(S2)
DELTA_L_85_OHMS_L1_5IN_DP: J9.2(S2) J10.1
DELTA_L_85_OHMS_L3_2IN_DN: J7.1 J8.2(S2)
DELTA_L_85_OHMS_L3_2IN_DP: J7.2(S2) J8.1
DELTA_L_85_OHMS_L3_5IN_DN: J11.1 J12.2(S2)
DELTA_L_85_OHMS_L3_5IN_DP: J11.2(S2) J12.1
DELTA_L_85_OHMS_L6_2IN_DN: J15.1 J16.2(S2)
DELTA_L_85_OHMS_L6_2IN_DP: J15.2(S2) J16.1
DELTA_L_85_OHMS_L6_5IN_DN: J19.1 J20.2(S2)
DELTA_L_85_OHMS_L6_5IN_DP: J19.2(S2) J20.1
DELTA_L_85_OHMS_L8_2IN_DN: J14.1 J17.2(S2)
DELTA_L_85_OHMS_L8_2IN_DP: J14.2(S2) J17.1
DELTA_L_85_OHMS_L8_5IN_DN: J18.1 J22.2(S2)
DELTA_L_85_OHMS_L8_5IN_DP: J18.2(S2) J22.1
FM_SLOT4_CFG0: J1.19 R8.2(B)
FM_SLOT4_CFG1: J1.18 R14.2(B)
FM_SLOT4_CFG2: J1.63 R16.2(B)
FM_SLOT4_CFG3: J1.66 R18.2(B)
J3_A1: J3.A1 R44.2(B)
J4_A1: J4.A1 R38.2(B)
J4_JTAG_NTRST: J4.B9 R41.2(B)
J4_JTAG_TCK: J4.A5 R43.2(B)
J4_JTAG_TDI: J4.A6 R40.1
J4_JTAG_TDO: J4.A7 R39.1
J4_JTAG_TMS: J4.A8 R42.1
JTAG_NTRST: J3.B9 R47.2(B) R58.1
JTAG_SLOT4_NTRST: J2.60 R58.2(B)
JTAG_SLOT4_TCK: J2.56 R56.2(B)
JTAG_SLOT4_TDI: J2.51 R51.2(B)
JTAG_SLOT4_TDO: J2.53 R50.2(B)
JTAG_SLOT4_TMS: J2.54 R55.2(B)
JTAG_TCK: J3.A5 R49.2(B) R56.1
JTAG_TDI: J3.A6 R46.1 R51.1
JTAG_TDO: J3.A7 R45.1 R50.1
JTAG_TMS: J3.A8 R48.1 R55.1
MUX_A0: R11.1 R12.2(B) U2.1
MUX_A1: R6.1 R7.2(B) U2.2
MUX_A2: R2.1 R3.2(B) U2.21
PE_CPU1_1A_RX_0_DN: J2.50 J4.A81
PE_CPU1_1A_RX_0_DP: J2.48 J4.A80
PE_CPU1_1A_RX_1_DN: J2.44 J4.A77
PE_CPU1_1A_RX_1_DP: J2.42 J4.A76
PE_CPU1_1A_RX_2_DN: J2.38 J4.A73
PE_CPU1_1A_RX_2_DP: J2.36 J4.A72
PE_CPU1_1A_RX_3_DN: J2.32 J4.A69
PE_CPU1_1A_RX_3_DP: J2.30 J4.A68
PE_CPU1_1A_TX_0_DN: J2.45 J4.B79
PE_CPU1_1A_TX_0_DP: J2.47 J4.B78
PE_CPU1_1A_TX_1_DN: J2.39 J4.B75
PE_CPU1_1A_TX_1_DP: J2.41 J4.B74
PE_CPU1_1A_TX_2_DN: J2.33 J4.B71
PE_CPU1_1A_TX_2_DP: J2.35 J4.B70
PE_CPU1_1A_TX_3_DN: J2.27 J4.B67
PE_CPU1_1A_TX_3_DP: J2.29 J4.B66
PE_CPU1_1B_RX_4_DN: J2.26 J4.A65
PE_CPU1_1B_RX_4_DP: J2.24 J4.A64
PE_CPU1_1B_RX_5_DN: J2.20 J4.A61
PE_CPU1_1B_RX_5_DP: J2.18 J4.A60
PE_CPU1_1B_RX_6_DN: J2.14 J4.A57
PE_CPU1_1B_RX_6_DP: J2.12 J4.A56
PE_CPU1_1B_RX_7_DN: J2.8 J4.A53
PE_CPU1_1B_RX_7_DP: J2.6 J4.A52
PE_CPU1_1B_TX_4_DN: J2.21 J4.B63
PE_CPU1_1B_TX_4_DP: J2.23 J4.B62
PE_CPU1_1B_TX_5_DN: J2.15 J4.B59
PE_CPU1_1B_TX_5_DP: J2.17 J4.B58
PE_CPU1_1B_TX_6_DN: J2.9 J4.B55
PE_CPU1_1B_TX_6_DP: J2.11 J4.B54
PE_CPU1_1B_TX_7_DN: J2.3 J4.B51
PE_CPU1_1B_TX_7_DP: J2.5 J4.B50
PE_CPU1_1C_RX_8_DN: J1.198 J4.A48
PE_CPU1_1C_RX_8_DP: J1.196 J4.A47
PE_CPU1_1C_RX_9_DN: J1.192 J4.A44
PE_CPU1_1C_RX_9_DP: J1.190 J4.A43
PE_CPU1_1C_RX_10_DN: J1.186 J4.A40
PE_CPU1_1C_RX_10_DP: J1.184 J4.A39
PE_CPU1_1C_RX_11_DN: J1.180 J4.A36
PE_CPU1_1C_RX_11_DP: J1.178 J4.A35
PE_CPU1_1C_TX_8_DN: J1.193 J4.B46
PE_CPU1_1C_TX_8_DP: J1.195 J4.B45
PE_CPU1_1C_TX_9_DN: J1.187 J4.B42
PE_CPU1_1C_TX_9_DP: J1.189 J4.B41
PE_CPU1_1C_TX_10_DN: J1.181 J4.B38
PE_CPU1_1C_TX_10_DP: J1.183 J4.B37
PE_CPU1_1C_TX_11_DN: J1.177 J4.B34
PE_CPU1_1C_TX_11_DP: J1.175 J4.B33
PE_CPU1_1D_RX_12_DN: J1.174 J4.A30
PE_CPU1_1D_RX_12_DP: J1.172 J4.A29
PE_CPU1_1D_RX_13_DN: J1.168 J4.A26
PE_CPU1_1D_RX_13_DP: J1.166 J4.A25
PE_CPU1_1D_RX_14_DN: J1.162 J4.A22
PE_CPU1_1D_RX_14_DP: J1.160 J4.A21
PE_CPU1_1D_RX_15_DN: J1.156 J4.A17
PE_CPU1_1D_RX_15_DP: J1.154 J4.A16
PE_CPU1_1D_TX_12_DN: J1.169 J4.B28
PE_CPU1_1D_TX_12_DP: J1.171 J4.B27
PE_CPU1_1D_TX_13_DN: J1.163 J4.B24
PE_CPU1_1D_TX_13_DP: J1.165 J4.B23
PE_CPU1_1D_TX_14_DN: J1.157 J4.B20
PE_CPU1_1D_TX_14_DP: J1.159 J4.B19
PE_CPU1_1D_TX_15_DN: J1.151 J4.B15
PE_CPU1_1D_TX_15_DP: J1.153 J4.B14
PE_CPU1_2A_RX_0_DN: J1.150 J3.A81
PE_CPU1_2A_RX_0_DP: J1.148 J3.A80
PE_CPU1_2A_RX_1_DN: J1.144 J3.A77
PE_CPU1_2A_RX_1_DP: J1.142 J3.A76
PE_CPU1_2A_RX_2_DN: J1.138 J3.A73
PE_CPU1_2A_RX_2_DP: J1.136 J3.A72
PE_CPU1_2A_RX_3_DN: J1.132 J3.A69
PE_CPU1_2A_RX_3_DP: J1.130 J3.A68
PE_CPU1_2A_TX_0_DN: J1.145 J3.B79
PE_CPU1_2A_TX_0_DP: J1.147 J3.B78
PE_CPU1_2A_TX_1_DN: J1.139 J3.B75
PE_CPU1_2A_TX_1_DP: J1.141 J3.B74
PE_CPU1_2A_TX_2_DN: J1.133 J3.B71
PE_CPU1_2A_TX_2_DP: J1.135 J3.B70
PE_CPU1_2A_TX_3_DN: J1.127 J3.B67
PE_CPU1_2A_TX_3_DP: J1.129 J3.B66
PE_CPU1_2B_RX_4_DN: J1.126 J3.A65
PE_CPU1_2B_RX_4_DP: J1.124 J3.A64
PE_CPU1_2B_RX_5_DN: J1.120 J3.A61
PE_CPU1_2B_RX_5_DP: J1.118 J3.A60
PE_CPU1_2B_RX_6_DN: J1.114 J3.A57
PE_CPU1_2B_RX_6_DP: J1.112 J3.A56
PE_CPU1_2B_RX_7_DN: J1.108 J3.A53
PE_CPU1_2B_RX_7_DP: J1.106 J3.A52
PE_CPU1_2B_TX_4_DN: J1.121 J3.B63
PE_CPU1_2B_TX_4_DP: J1.123 J3.B62
PE_CPU1_2B_TX_5_DN: J1.115 J3.B59
PE_CPU1_2B_TX_5_DP: J1.117 J3.B58
PE_CPU1_2B_TX_6_DN: J1.109 J3.B55
PE_CPU1_2B_TX_6_DP: J1.111 J3.B54
PE_CPU1_2B_TX_7_DN: J1.103 J3.B51
PE_CPU1_2B_TX_7_DP: J1.105 J3.B50
PE_CPU1_2C_RX_8_DN: J1.102 J3.A48
PE_CPU1_2C_RX_8_DP: J1.100 J3.A47
PE_CPU1_2C_RX_9_DN: J1.96 J3.A44
PE_CPU1_2C_RX_9_DP: J1.94 J3.A43
PE_CPU1_2C_RX_10_DN: J1.90 J3.A40
PE_CPU1_2C_RX_10_DP: J1.88 J3.A39
PE_CPU1_2C_RX_11_DN: J1.84 J3.A36
PE_CPU1_2C_RX_11_DP: J1.82 J3.A35
PE_CPU1_2C_TX_8_DN: J1.97 J3.B45
PE_CPU1_2C_TX_8_DP: J1.99 J3.B46
PE_CPU1_2C_TX_9_DN: J1.91 J3.B41
PE_CPU1_2C_TX_9_DP: J1.93 J3.B42
PE_CPU1_2C_TX_10_DN: J1.85 J3.B37
PE_CPU1_2C_TX_10_DP: J1.87 J3.B38
PE_CPU1_2C_TX_11_DN: J1.79 J3.B33
PE_CPU1_2C_TX_11_DP: J1.81 J3.B34
PE_CPU1_2D_RX_12_DN: J1.78 J3.A30
PE_CPU1_2D_RX_12_DP: J1.76 J3.A29
PE_CPU1_2D_RX_13_DN: J1.72 J3.A26
PE_CPU1_2D_RX_13_DP: J1.70 J3.A25
PE_CPU1_2D_RX_14_DN: J1.62 J3.A22
PE_CPU1_2D_RX_14_DP: J1.60 J3.A21
PE_CPU1_2D_RX_15_DN: J1.56 J3.A17
PE_CPU1_2D_RX_15_DP: J1.54 J3.A16
PE_CPU1_2D_TX_12_DN: J1.73 J3.B27
PE_CPU1_2D_TX_12_DP: J1.75 J3.B28
PE_CPU1_2D_TX_13_DN: J1.67 J3.B23
PE_CPU1_2D_TX_13_DP: J1.69 J3.B24
PE_CPU1_2D_TX_14_DN: J1.57 J3.B19
PE_CPU1_2D_TX_14_DP: J1.59 J3.B20
PE_CPU1_2D_TX_15_DN: J1.51 J3.B14
PE_CPU1_2D_TX_15_DP: J1.53 J3.B15
PWRBRK_J3_N: J3.B30 R99.1 U1.6
PWRBRK_J4_N: J4.B30 R98.1 U1.4(Y2)
PWRBRK_SLOT4_N: J1.20 R74.2(B) U1.1 U1.3
RST_J3_N: R26.2(B) U6.2
RST_J3_TRI_N: J3.A11 U6.4(Y)
RST_J4_N: R52.2(B) U7.2
RST_J4_TRI_N: J4.A11 U7.4(Y)
RST_N: R112.1 U2.3
RST_P1_SLOT4_N: J1.29 R26.1 R52.1
SLOT4_PRSNT_R_N: J1.199 R29.2(B)
SLOT4_WAKE_R_N: J1.28 R1.1 R54.1
SMB_0_ISO_SCL: J4.B5 Q1.2(SRC) R59.2(B) R102.1
SMB_0_ISO_SDA: J4.B6 Q2.2(SRC) R60.2(B) R103.1
SMB_0_R_SCL: Q1.3 R33.2(B) R59.1 R108.1
SMB_0_R_SDA: Q2.3 R32.2(B) R60.1 R109.1
SMB_0_SCL: R33.1 U2.5
SMB_0_SDA: R32.1 U2.4
SMB_1_ISO_SCL: J3.B5 Q4.2(SRC) R62.2(B) R101.1
SMB_1_ISO_SDA: J3.B6 Q3.2(SRC) R61.2(B) R100.1
SMB_1_R_SCL: Q4.3 R35.2(B) R62.1 R106.1
SMB_1_R_SDA: Q3.3 R34.2(B) R61.1 R107.1
SMB_1_SCL: R35.1 U2.7
SMB_1_SDA: R34.1 U2.6
SMB_2_SCL: R64.1 U2.9
SMB_2_SDA: R63.1 U2.8
SMB_3_SCL: R66.1 U2.11
SMB_3_SDA: R65.1 U2.10
SMB_3V3_CLK_P1: R21.2(B) R25.1
SMB_3V3_SCL: R23.1 R57.2(B)
SMB_3V3_SDA: R19.2(B) R22.1
SMB_3V3_SDA_P1: R20.2(B) R24.1
SMB_4_SCL: R68.1 U2.14
SMB_4_SDA: R67.1 U2.13
SMB_5_SCL: R70.1 U2.16
SMB_5_SDA: R69.1 U2.15
SMB_6_SCL: R30.2(B) R36.2(B) R111.1 U2.18
SMB_6_SDA: R31.2(B) R37.2(B) R110.1 U2.17
SMB_7_SCL: R72.1 U2.20
SMB_7_SDA: R71.1 U2.19
SMB_FRU_SCL: R30.1 U5.6
SMB_FRU_SDA: R31.1 U5.5
SMB_SENSOR_SCL: R36.1 U4.10
SMB_SENSOR_SDA: R37.1 U4.9
SMB_SLOT4_3V3_CLK_R_P1: J1.32 R21.1
SMB_SLOT4_3V3_R_SCL: J1.17 R57.1 U2.22
SMB_SLOT4_3V3_R_SDA: J1.15 R19.1 U2.23
SMB_SLOT4_3V3_SDA_R_P1: J1.30 R20.1
TDR_50_OHMS_L1: TDR5.2
TDR_50_OHMS_L3: TDR6.2
TDR_50_OHMS_L8: TDR8.2
TDR_85_OHMS_L1_DN: TDR1.3
TDR_85_OHMS_L1_DP: TDR1.2
TDR_85_OHMS_L3_DN: TDR2.3
TDR_85_OHMS_L3_DP: TDR2.2
TDR_85_OHMS_L6_DN: TDR3.3
TDR_85_OHMS_L6_DP: TDR3.2
TDR_85_OHMS_L8_DN: TDR4.3
TDR_85_OHMS_L8_DP: TDR4.2
THERM_N: R104.1 U4.7
U2_A0: R13.1 R15.2(B) U5.1
U2_A1: R9.1 R10.2(B) U5.2
U2_A2: R4.1 R5.2(B) U5.3
U2_WP: R17.1 R27.2(B) U5.7(WP)
U4_DN1: C30.2(B) Q5.2(E) U4.3
U4_DN2: C32.1 Q6.2(E) U4.5
U4_DP1: C30.1 Q5.1 Q5.3 U4.2
U4_DP2: C32.2(B) Q6.1 Q6.3 U4.4
WAKE_J4_N: J4.B11 R54.2(B)
WAKE_R_N: J3.B11 R1.2(B)

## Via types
v1: diameter 0.508, hole 0.254, TOP to BOTTOM, 1685 vias

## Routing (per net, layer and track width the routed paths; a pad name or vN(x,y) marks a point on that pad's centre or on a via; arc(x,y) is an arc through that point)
GND: length 301.4
  TOP w0.254: v1(84.33,24) 84.2,24.14 U4.6 ; R18.1 v1(93.24,8.86) ; R44.1 v1(127.64,13.92) ; R43.1 v1(119.89,32.13) ; R8.1 v1(112.45,9.5) R14.1 ; R16.1 v1(94.44,8.86) ; R29.1 v1(38.13,8.86) ; R38.1 v1(127.64,33.86) ; R41.1 v1(114.3,32.13)
  TOP w0.305: 126.19,48.46 C22.2 ; C22.2 126.75,49 ; C22.2 127.31,48.46 ; 122.63,28.14 C2.2 ; C2.2 123.75,28.14 ; C2.2 123.19,28.68 ; C21.2 121.97,48.46 ; C21.2 120.85,48.46 ; C21.2 121.41,49 ; C7.2 119.51,28.35 ; C7.2 119.07,27.97 ; C7.2 119.94,27.97 ; 111.84,28.14 C10.2 ; C10.2 112.39,28.68 ; C10.2 112.95,28.14 ; 124.41,28.14 C8.2 ; C8.2 125.53,28.14 ; C8.2 124.97,28.68 ; C6.2 118.92,27.97 ; C6.2 118.49,28.35 ; C6.2 118.06,27.97 ; 122.63,48.46 C29.2 ; C29.2 123.19,49 ; C29.2 123.75,48.46 ; J13.1 26.98,83.1 ; J13.1 26.07,82.2 ; J13.1 25.17,83.1 ; J13.1 26.07,84 ; 119.07,48.29 C25.2 ; C25.2 119.94,48.29 ; C25.2 119.51,48.67 ; C27.2 118.92,48.29 ; C27.2 118.06,48.29 ; C27.2 118.49,48.67 ; C9.2 126.75,28.68 ; C9.2 126.19,28.14 ; C9.2 127.31,28.14 ; 111.84,48.46 C31.2 ; C31.2 112.39,47.93 ; C31.2 112.39,49 ; C28.2 125.53,48.46 ; C28.2 124.41,48.46 ; C28.2 124.97,49 ; 117.04,48.29 C26.2 ; C26.2 117.47,48.67 ; C26.2 117.91,48.29 ; 26.07,79.2 J13.3 ; J13.3 26.98,80.1 ; J13.3 26.07,81 ; J13.3 25.17,80.1 ; 120.85,28.14 C1.2 ; C1.2 121.97,28.14 ; C1.2 121.41,28.68 ; C5.2 117.91,27.97 ; C5.2 117.47,28.35 ; C5.2 117.04,27.97
  TOP w0.406: R47.1 v1(113.26,12.29) ; C15.2 v1(83.97,44.93) ; U7.3 v1(112.03,32.26) ; R3.1 v1(95.76,44.27) ; v1(88.77,56.21) 89.14,55.84 U2.12 ; C17.2 v1(75.29,25.22) ; R49.1 v1(116.18,12.29) ; v1(111.27,10.41) 111.14,10.29 U6.3 ; R5.1 v1(79.88,59.82) ; R10.1 v1(81.92,59.82) ; v1(108.84,32.52) C33.2 ; R27.1 v1(82.3,44.27) ; C34.2 v1(111.28,12.42) ; R7.1 v1(96.27,59.82) ; C16.2 v1(98.45,44.93) ; R15.1 v1(83.95,59.82) ; U1.2 103.24,14.12 J3.A20 ; R12.1 v1(98.3,59.82) ; C14.2 v1(103.92,8.82)
  TOP w0.508: J1.34 107.33,4.68 v1(107.73,5.08) ; v1(47.73,5.08) 47.33,4.68 J1.176 ; J1.26 110.53,4.28 110.13,4.68 v1(110.13,5.08) ; J1.188 42.53,4.68 v1(42.93,5.08) ; J1.152 56.93,4.68 v1(57.33,5.08) ; v1(105.33,5.08) 104.93,4.68 J1.40 ; U5.4 v1(79.25,55.85) ; J1.170 49.73,4.68 v1(50.13,5.08) ; v1(95.73,5.08) 95.33,4.68 J1.64 ; v1(86.13,5.08) 85.73,4.68 J1.80 ; J1.13 v1(115.33,5.08) v1(115.33,6.1) ; J2.40 11.52,4.68 v1(11.92,5.08) ; J1.146 59.33,4.68 v1(59.73,5.08) ; v1(38.13,5.08) 37.73,4.68 J1.200 ; v1(78.93,5.08) 78.53,4.68 J1.98 ; J1.182 44.93,4.68 v1(45.33,5.08) ; J1.46 102.53,4.68 v1(102.93,5.08) ; J1.128 66.53,4.68 v1(66.93,5.08) ; J2.28 16.32,4.68 v1(16.72,5.08) ; v1(74.13,5.08) 73.73,4.68 J1.110 ; J2.52 6.72,4.68 v1(7.12,5.08) ; v1(90.93,5.08) 90.53,4.68 J1.68 ; v1(83.73,5.08) 83.33,4.68 J1.86 ; v1(88.53,5.08) 88.13,4.68 J1.74 ; v1(23.93,5.08) 23.52,4.68 J2.10 ; J1.52 100.13,4.68 v1(100.53,5.08) ; v1(98.13,5.08) 97.73,4.68 J1.58 ; v1(40.53,5.08) 40.13,4.68 J1.194 ; v1(62.13,5.08) 61.73,4.68 J1.140 ; v1(14.32,5.08) 13.92,4.68 J2.34 ; J2.46 9.12,4.68 v1(9.53,5.08) ; v1(26.32,5.08) 25.92,4.68 J2.4 ; v1(69.33,5.08) 68.93,4.68 J1.122 ; v1(71.73,5.08) 71.33,4.68 J1.116 ; J1.92 80.93,4.68 v1(81.33,5.08) ; J1.134 64.13,4.68 v1(64.53,5.08) ; v1(21.52,5.08) 21.12,4.68 J2.16 ; v1(54.93,5.08) 54.53,4.68 J1.158 ; v1(52.53,5.08) 52.13,4.68 J1.164 ; J2.58 4.32,4.68 v1(4.72,5.08) ; v1(19.12,5.08) 18.72,4.68 J2.22 ; J1.104 76.13,4.68 v1(76.53,5.08)
  L3 w0.305: J13.3 26.07,81 ; J13.3 26.98,80.1 ; J13.3 26.07,79.2 ; J13.3 25.17,80.1 ; J13.1 26.98,83.1 ; J13.1 26.07,82.2 ; J13.1 26.07,84 ; J13.1 25.17,83.1
  BOTTOM w0.305: J13.3 26.07,81 ; J13.3 25.17,80.1 ; J13.3 26.07,79.2 ; J13.3 26.98,80.1 ; J13.1 26.07,84 ; J13.1 26.98,83.1 ; J13.1 25.17,83.1 ; J13.1 26.07,82.2
  BOTTOM w0.508: J1.65 91.33,4.68 v1(90.93,5.08) ; v1(83.73,5.08) 84.13,4.68 J1.83 ; J1.137 62.53,4.68 v1(62.13,5.08) ; v1(7.12,5.08) 7.52,4.68 J2.49 ; J2.13 21.92,4.68 v1(21.52,5.08) ; J1.107 74.53,4.68 v1(74.13,5.08) ; v1(42.93,5.08) 43.33,4.68 J1.185 ; J1.71 88.93,4.68 v1(88.53,5.08) ; v1(14.32,5.08) 14.72,4.68 J2.31 ; v1(23.93,5.08) 24.32,4.68 J2.7 ; J1.77 86.53,4.68 v1(86.13,5.08) ; J1.125 67.33,4.68 v1(66.93,5.08) ; J1.167 50.53,4.68 v1(50.13,5.08) ; J1.37 105.73,4.68 v1(105.33,5.08) ; J1.119 69.73,4.68 v1(69.33,5.08) ; v1(102.93,5.08) 103.33,4.68 J1.43 ; v1(95.73,5.08) 96.13,4.68 J1.61 ; J1.143 60.13,4.68 v1(59.73,5.08) ; v1(47.73,5.08) 48.13,4.68 J1.173 ; J1.179 45.73,4.68 v1(45.33,5.08) ; v1(78.93,5.08) 79.33,4.68 J1.95 ; v1(64.53,5.08) 64.93,4.68 J1.131 ; v1(9.53,5.08) 9.92,4.68 J2.43 ; J1.89 81.73,4.68 v1(81.33,5.08) ; J2.55 5.12,4.68 v1(4.72,5.08) ; J1.55 98.53,4.68 v1(98.13,5.08) ; v1(107.73,5.08) 108.13,4.68 J1.31 ; v1(52.53,5.08) 52.93,4.68 J1.161 ; v1(54.93,5.08) 55.33,4.68 J1.155 ; v1(76.53,5.08) 76.93,4.68 J1.101 ; J2.19 19.52,4.68 v1(19.12,5.08) ; v1(16.72,5.08) 17.12,4.68 J2.25 ; J1.197 38.53,4.68 v1(38.13,5.08) ; J1.49 100.93,4.68 v1(100.53,5.08) ; J1.113 72.13,4.68 v1(71.73,5.08) ; v1(57.33,5.08) 57.73,4.68 J1.149 ; J1.13 v1(115.33,5.08) 115.33,5.33 v1(115.33,6.1) ; v1(26.32,5.08) 26.72,4.68 J2.1 ; J1.191 40.93,4.68 v1(40.53,5.08) ; v1(11.92,5.08) 12.32,4.68 J2.37
  vias: v1(7.12,7.87) v1(9.53,7.87) v1(11.92,7.87) v1(14.32,7.87) v1(16.72,7.87) v1(19.12,7.87) v1(21.52,7.87) v1(23.02,84.2) v1(23.02,83.19) v1(23.02,82.17) v1(23.02,81.2) v1(23.02,80.19) v1(23.02,79.17) v1(23.93,7.87) v1(24.03,84.2) v1(24.03,83.19) v1(24.03,82.17) v1(24.03,81.2) v1(24.03,80.19) v1(24.03,79.17) v1(38.13,7.87) v1(40.53,33.26) v1(40.53,7.87) v1(42.93,7.87) v1(43.15,33.26) v1(44.53,33.26) v1(45.33,7.87) v1(47.15,33.26) v1(47.73,7.87) v1(48.53,33.26) v1(50.13,7.87) v1(51.15,33.26) v1(52.53,33.26) v1(52.53,7.87) v1(54.93,7.87) v1(55.15,33.26) v1(56.53,33.26) v1(57.33,7.87) v1(59.15,33.26) v1(59.73,7.87) v1(60.53,33.26) v1(62.13,7.87) v1(63.15,33.26) v1(64.53,33.26) v1(64.53,7.87) v1(66.93,7.87) v1(67.15,33.26) v1(68.53,33.26) v1(69.33,7.87) v1(71.15,33.26) v1(71.73,7.87) v1(74.13,7.87) v1(74.53,33.26) v1(76.53,7.87) v1(77.15,33.26) v1(78.53,33.26) v1(78.84,43.46) v1(78.93,7.87) v1(80.67,43.46) v1(81.15,33.26) v1(81.33,7.87) v1(82.53,33.26) v1(83.73,7.87) v1(85.15,33.26) v1(86.13,7.87) v1(86.53,33.26) v1(88.1,27.39) v1(88.1,26.37) v1(88.53,7.87) v1(89.15,33.26) v1(91.69,59.82) v1(91.74,46.91) v1(92.53,33.26) v1(92.71,59.82) v1(93.47,46.35) v1(93.73,59.82) v1(95.15,33.26) v1(96.53,33.26) v1(98.15,53.06) v1(98.15,48.79) v1(98.13,7.87) v1(99.15,33.26) v1(99.57,52.39) v1(99.57,49.34) v1(100.53,33.26) v1(100.53,7.87) v1(102.49,23.84) v1(103.15,33.26) v1(103.89,23.84) v1(104.53,33.26) v1(105.33,7.87) v1(105.68,47.78) v1(107.04,44.3) v1(107.04,23.98) v1(107.15,33.26) v1(108.81,44.3) v1(108.81,23.98) v1(108.9,30.1) v1(109.23,47.78) v1(109.29,29.08) v1(110.24,30.1) v1(112.39,49.23) v1(112.39,28.91) v1(113.73,49.25) v1(113.73,28.93) v1(114.62,49.25) v1(114.62,28.93) v1(115.63,49.25) v1(115.63,28.93) v1(116.52,49.25) v1(116.52,28.93) v1(117.47,48.9) v1(117.47,28.57) v1(118.49,48.9) v1(118.49,28.57) v1(119.51,48.9) v1(119.51,28.57) v1(121.41,49.23) v1(121.41,28.91) v1(123.19,49.23) v1(123.19,28.91) v1(124.97,49.23) v1(124.97,28.91) v1(126.75,49.23) v1(126.75,28.91) v1(128.33,50.41) v1(128.33,30.21) v1(129.48,50.41) v1(129.48,30.21) v1(131.25,50.41) v1(131.25,30.21) v1(132.4,50.41) v1(132.4,30.21) v1(134.24,50.55) v1(134.24,30.35) v1(135,50.55) v1(135,30.35) v1(135.76,50.55) v1(135.76,30.35) v1(137.79,50.55) v1(137.79,30.35) v1(138.56,50.55) v1(138.56,30.35) v1(139.32,50.55) v1(139.32,30.35)
GND_D:
  vias: v1(-8.51,348.74) v1(-8.51,338.6) v1(-7.51,348.74) v1(-7.51,338.6) v1(-6.51,348.74) v1(-6.51,338.6) v1(-5.52,348.74) v1(-5.52,338.6) v1(-4.52,348.74) v1(-4.52,338.6) v1(-3.52,348.74) v1(-3.52,338.6) v1(-2.52,348.74) v1(-2.52,343.67) v1(-2.52,338.6) v1(-1.52,348.74) v1(-1.52,343.67) v1(-1.52,338.6) v1(2.8,348.74) v1(2.8,343.67) v1(2.8,338.6) v1(3.79,348.74) v1(3.79,343.67) v1(3.79,338.6) v1(4.79,348.74) v1(4.79,343.67) v1(4.79,338.6) v1(5.79,348.74) v1(5.79,343.67) v1(5.79,338.6) v1(6.79,348.74) v1(6.79,343.67) v1(6.79,338.6) v1(7.79,348.74) v1(7.79,343.67) v1(7.79,338.6) v1(8.79,348.74) v1(8.79,343.67) v1(8.79,338.6) v1(9.78,348.74) v1(9.78,343.67) v1(9.78,338.6) v1(10.78,348.74) v1(10.78,343.67) v1(10.78,338.6) v1(11.78,348.74) v1(11.78,343.67) v1(11.78,338.6) v1(12.78,348.74) v1(12.78,343.67) v1(12.78,338.6) v1(13.78,348.74) v1(13.78,343.67) v1(13.78,338.6) v1(14.77,348.74) v1(14.77,343.67) v1(14.77,338.6) v1(15.77,348.74) v1(15.77,343.67) v1(15.77,338.6) v1(16.77,348.74) v1(16.77,343.67) v1(16.77,338.6) v1(17.77,348.74) v1(17.77,343.67) v1(17.77,338.6) v1(18.77,348.74) v1(18.77,343.67) v1(18.77,338.6) v1(19.77,348.74) v1(19.77,343.67) v1(19.77,338.6) v1(20.76,348.74) v1(20.76,343.67) v1(20.76,338.6) v1(21.76,348.74) v1(21.76,343.67) v1(21.76,338.6) v1(22.76,348.74) v1(22.76,343.67) v1(22.76,338.6) v1(23.76,348.74) v1(23.76,343.67) v1(23.76,338.6) v1(24.76,348.74) v1(24.76,343.67) v1(24.76,338.6) v1(25.76,348.74) v1(25.76,343.67) v1(25.76,338.6) v1(26.75,348.74) v1(26.75,343.67) v1(26.75,338.6) v1(27.75,348.74) v1(27.75,343.67) v1(27.75,338.6) v1(28.75,348.74) v1(28.75,343.67) v1(28.75,338.6) v1(29.75,348.74) v1(29.75,343.67) v1(29.75,338.6) v1(30.75,348.74) v1(30.75,343.67) v1(30.75,338.6) v1(31.74,348.74) v1(31.74,343.67) v1(31.74,338.6) v1(32.74,348.74) v1(32.74,343.67) v1(32.74,338.6) v1(33.74,348.74) v1(33.74,343.67) v1(33.74,338.6) v1(34.74,348.74) v1(34.74,343.67) v1(34.74,338.6) v1(35.74,348.74) v1(35.74,343.67) v1(35.74,338.6) v1(36.74,348.74) v1(36.74,343.67) v1(36.74,338.6) v1(37.73,348.74) v1(37.73,343.67) v1(37.73,338.6) v1(38.73,348.74) v1(38.73,343.67) v1(38.73,338.6) v1(39.73,348.74) v1(39.73,343.67) v1(39.73,338.6) v1(40.73,348.74) v1(40.73,343.67) v1(40.73,338.6) v1(41.73,348.74) v1(41.73,343.67) v1(41.73,338.6) v1(42.73,348.74) v1(42.73,343.67) v1(42.73,338.6) v1(43.72,348.74) v1(43.72,343.67) v1(43.72,338.6) v1(44.72,348.74) v1(44.72,343.67) v1(44.72,338.6) v1(45.72,348.74) v1(45.72,343.67) v1(45.72,338.6) v1(46.72,348.74) v1(46.72,343.67) v1(46.72,338.6) v1(47.72,348.74) v1(47.72,343.67) v1(47.72,338.6) v1(48.71,348.74) v1(48.71,343.67) v1(48.71,338.6) v1(49.71,348.74) v1(49.71,343.67) v1(49.71,338.6) v1(50.71,348.74) v1(50.71,343.67) v1(50.71,338.6) v1(51.71,348.74) v1(51.71,343.67) v1(51.71,338.6) v1(52.71,348.74) v1(52.71,343.67) v1(52.71,338.6) v1(57.41,348.74) v1(57.41,343.67) v1(57.41,338.6) v1(58.4,348.74) v1(58.4,343.67) v1(58.4,338.6) v1(63.01,348.74) v1(63.01,343.67) v1(63.01,338.6) v1(64.01,348.74) v1(64.01,343.67) v1(64.01,338.6) v1(65.01,348.74) v1(65.01,343.67) v1(65.01,338.6) v1(66.01,348.74) v1(66.01,343.67) v1(66.01,338.6) v1(67.01,348.74) v1(67.01,343.67) v1(67.01,338.6) v1(68,348.74) v1(68,343.67) v1(68,338.6) v1(69,348.74) v1(69,343.67) v1(69,338.6) v1(70,348.74) v1(70,343.67) v1(70,338.6) v1(71,348.74) v1(71,343.67) v1(71,338.6) v1(72,348.74) v1(72,343.67) v1(72,338.6) v1(73,348.74) v1(73,343.67) v1(73,338.6) v1(73.99,348.74) v1(73.99,343.67) v1(73.99,338.6) v1(74.99,348.74) v1(74.99,343.67) v1(74.99,338.6) v1(75.99,348.74) v1(75.99,343.67) v1(75.99,338.6) v1(76.99,348.74) v1(76.99,343.67) v1(76.99,338.6) v1(77.99,348.74) v1(77.99,343.67) v1(77.99,338.6) v1(78.98,348.74) v1(78.98,343.67) v1(78.98,338.6) v1(79.98,348.74) v1(79.98,343.67) v1(79.98,338.6) v1(80.98,348.74) v1(80.98,343.67) v1(80.98,338.6) v1(81.98,348.74) v1(81.98,343.67) v1(81.98,338.6) v1(82.98,348.74) v1(82.98,343.67) v1(82.98,338.6) v1(83.98,348.74) v1(83.98,343.67) v1(83.98,338.6) v1(84.97,348.74) v1(84.97,343.67) v1(84.97,338.6) v1(85.97,348.74) v1(85.97,343.67) v1(85.97,338.6) v1(86.97,348.74) v1(86.97,343.67) v1(86.97,338.6) v1(87.97,348.74) v1(87.97,343.67) v1(87.97,338.6) v1(88.97,348.74) v1(88.97,343.67) v1(88.97,338.6) v1(89.97,348.74) v1(89.97,343.67) v1(89.97,338.6) v1(90.96,348.74) v1(90.96,343.67) v1(90.96,338.6) v1(91.96,348.74) v1(91.96,343.67) v1(91.96,338.6) v1(92.96,348.74) v1(92.96,343.67) v1(92.96,338.6) v1(93.96,348.74) v1(93.96,343.67) v1(93.96,338.6) v1(94.96,348.74) v1(94.96,343.67) v1(94.96,338.6) v1(95.95,348.74) v1(95.95,343.67) v1(95.95,338.6) v1(96.95,348.74) v1(96.95,343.67) v1(96.95,338.6) v1(97.95,348.74) v1(97.95,343.67) v1(97.95,338.6) v1(98.95,348.74) v1(98.95,343.67) v1(98.95,338.6) v1(99.95,348.74) v1(99.95,343.67) v1(99.95,338.6) v1(100.95,348.74) v1(100.95,343.67) v1(100.95,338.6) v1(101.94,348.74) v1(101.94,343.67) v1(101.94,338.6) v1(102.94,348.74) v1(102.94,343.67) v1(102.94,338.6) v1(103.94,348.74) v1(103.94,343.67) v1(103.94,338.6) v1(104.94,348.74) v1(104.94,343.67) v1(104.94,338.6) v1(105.94,348.74) v1(105.94,343.67) v1(105.94,338.6) v1(106.94,348.74) v1(106.94,343.67) v1(106.94,338.6) v1(107.93,348.74) v1(107.93,343.67) v1(107.93,338.6) v1(108.93,348.74) v1(108.93,343.67) v1(108.93,338.6) v1(109.93,348.74) v1(109.93,343.67) v1(109.93,338.6) v1(110.93,348.74) v1(110.93,343.67) v1(110.93,338.6) v1(111.93,348.74) v1(111.93,343.67) v1(111.93,338.6) v1(112.92,348.74) v1(112.92,343.67) v1(112.92,338.6) v1(113.92,348.74) v1(113.92,343.67) v1(113.92,338.6) v1(114.92,348.74) v1(114.92,343.67) v1(114.92,338.6) v1(115.92,348.74) v1(115.92,343.67) v1(115.92,338.6) v1(116.92,348.74) v1(116.92,343.67) v1(116.92,338.6) v1(117.92,348.74) v1(117.92,343.67) v1(117.92,338.6) v1(118.91,348.74) v1(118.91,343.67) v1(118.91,338.6) v1(119.91,348.74) v1(119.91,343.67) v1(119.91,338.6) v1(120.91,348.74) v1(120.91,343.67) v1(120.91,338.6) v1(121.91,348.74) v1(121.91,343.67) v1(121.91,338.6) v1(122.91,348.74) v1(122.91,343.67) v1(122.91,338.6) v1(123.9,348.74) v1(123.9,343.67) v1(123.9,338.6) v1(124.9,348.74) v1(124.9,343.67) v1(124.9,338.6) v1(125.9,348.74) v1(125.9,343.67) v1(125.9,338.6) v1(126.9,348.74) v1(126.9,343.67) v1(126.9,338.6) v1(127.9,348.74) v1(127.9,343.67) v1(127.9,338.6) v1(128.9,348.74) v1(128.9,343.67) v1(128.9,338.6) v1(129.89,348.74) v1(129.89,343.67) v1(129.89,338.6) v1(130.89,348.74) v1(130.89,343.67) v1(130.89,338.6) v1(131.89,348.74) v1(131.89,343.67) v1(131.89,338.6) v1(132.89,348.74) v1(132.89,343.67) v1(132.89,338.6) v1(133.89,348.74) v1(133.89,343.67) v1(133.89,338.6) v1(134.89,348.74) v1(134.89,343.67) v1(134.89,338.6) v1(135.88,348.74) v1(135.88,343.67) v1(135.88,338.6) v1(136.88,348.74) v1(136.88,343.67) v1(136.88,338.6) v1(137.88,348.74) v1(137.88,343.67) v1(137.88,338.6) v1(138.88,348.74) v1(138.88,343.67) v1(138.88,338.6) v1(139.88,348.74) v1(139.88,343.67) v1(139.88,338.6) v1(140.87,348.74) v1(140.87,343.67) v1(140.87,338.6) v1(141.87,348.74) v1(141.87,343.67) v1(141.87,338.6) v1(142.87,348.74) v1(142.87,343.67) v1(142.87,338.6) v1(143.87,348.74) v1(143.87,343.67) v1(143.87,338.6) v1(144.87,348.74) v1(144.87,343.67) v1(144.87,338.6) v1(145.87,348.74) v1(145.87,343.67) v1(145.87,338.6) v1(146.86,348.74) v1(146.86,343.67) v1(146.86,338.6) v1(147.86,348.74) v1(147.86,343.67) v1(147.86,338.6) v1(148.86,348.74) v1(148.86,343.67) v1(148.86,338.6) v1(149.86,348.74) v1(149.86,343.67) v1(149.86,338.6) v1(150.86,348.74) v1(150.86,343.67) v1(150.86,338.6) v1(151.85,348.74) v1(151.85,343.67) v1(151.85,338.6) v1(152.85,348.74) v1(152.85,343.67) v1(152.85,338.6) v1(153.85,348.74) v1(153.85,343.67) v1(153.85,338.6) v1(154.85,348.74) v1(154.85,343.67) v1(154.85,338.6) v1(155.85,348.74) v1(155.85,343.67) v1(155.85,338.6) v1(156.85,348.74) v1(156.85,343.67) v1(156.85,338.6) v1(157.84,348.74) v1(157.84,343.67) v1(157.84,338.6) v1(158.84,348.74) v1(158.84,343.67) v1(158.84,338.6) v1(159.84,348.74) v1(159.84,343.67) v1(159.84,338.6) v1(160.84,348.74) v1(160.84,343.67) v1(160.84,338.6) v1(161.84,348.74) v1(161.84,343.67) v1(161.84,338.6) v1(162.84,348.74) v1(162.84,343.67) v1(162.84,338.6) v1(163.83,348.74) v1(163.83,343.67) v1(163.83,338.6) v1(164.83,348.74) v1(164.83,343.67) v1(164.83,338.6) v1(165.83,348.74) v1(165.83,343.67) v1(165.83,338.6) v1(166.83,348.74) v1(166.83,343.67) v1(166.83,338.6) v1(167.83,348.74) v1(167.83,343.67) v1(167.83,338.6) v1(168.82,348.74) v1(168.82,343.67) v1(168.82,338.6) v1(169.82,348.74) v1(169.82,343.67) v1(169.82,338.6) v1(170.82,348.74) v1(170.82,343.67) v1(170.82,338.6) v1(171.82,348.74) v1(171.82,343.67) v1(171.82,338.6) v1(172.82,348.74) v1(172.82,343.67) v1(172.82,338.6) v1(173.82,348.74) v1(173.82,343.67) v1(173.82,338.6) v1(174.81,348.74) v1(174.81,343.67) v1(174.81,338.6) v1(175.81,348.74) v1(175.81,343.67) v1(175.81,338.6) v1(176.81,348.74) v1(176.81,343.67) v1(176.81,338.6) v1(177.81,348.74) v1(177.81,343.67) v1(177.81,338.6) v1(178.81,348.74) v1(178.81,343.67) v1(178.81,338.6) v1(179.81,348.74) v1(179.81,343.67) v1(179.81,338.6) v1(180.8,348.74) v1(180.8,343.67) v1(180.8,338.6) v1(181.8,348.74) v1(181.8,343.67) v1(181.8,338.6) v1(182.8,348.74) v1(182.8,343.67) v1(182.8,338.6) v1(183.8,348.74) v1(183.8,343.67) v1(183.8,338.6) v1(184.8,348.74) v1(184.8,343.67) v1(184.8,338.6) v1(185.79,348.74) v1(185.79,343.67) v1(185.79,338.6) v1(186.79,348.74) v1(186.79,343.67) v1(186.79,338.6) v1(187.79,348.74) v1(187.79,343.67) v1(187.79,338.6) v1(192.53,348.74) v1(192.53,343.67) v1(192.53,338.6) v1(193.53,348.74) v1(193.53,343.67) v1(193.53,338.6) v1(194.52,348.74) v1(194.52,338.6) v1(195.52,348.74) v1(195.52,338.6) v1(196.52,348.74) v1(196.52,338.6) v1(197.52,348.74) v1(197.52,338.6) v1(198.52,348.74) v1(198.52,338.6)
